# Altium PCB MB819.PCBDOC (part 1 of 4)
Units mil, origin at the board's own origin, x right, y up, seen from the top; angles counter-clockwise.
Board outline 4505 x 6805 mil, 4 copper layers (TopLayer, MidLayer1, GND, BottomLayer), stack 69.6 mil thick; 336 components, 282 nets, 1318 pads, 584 vias.
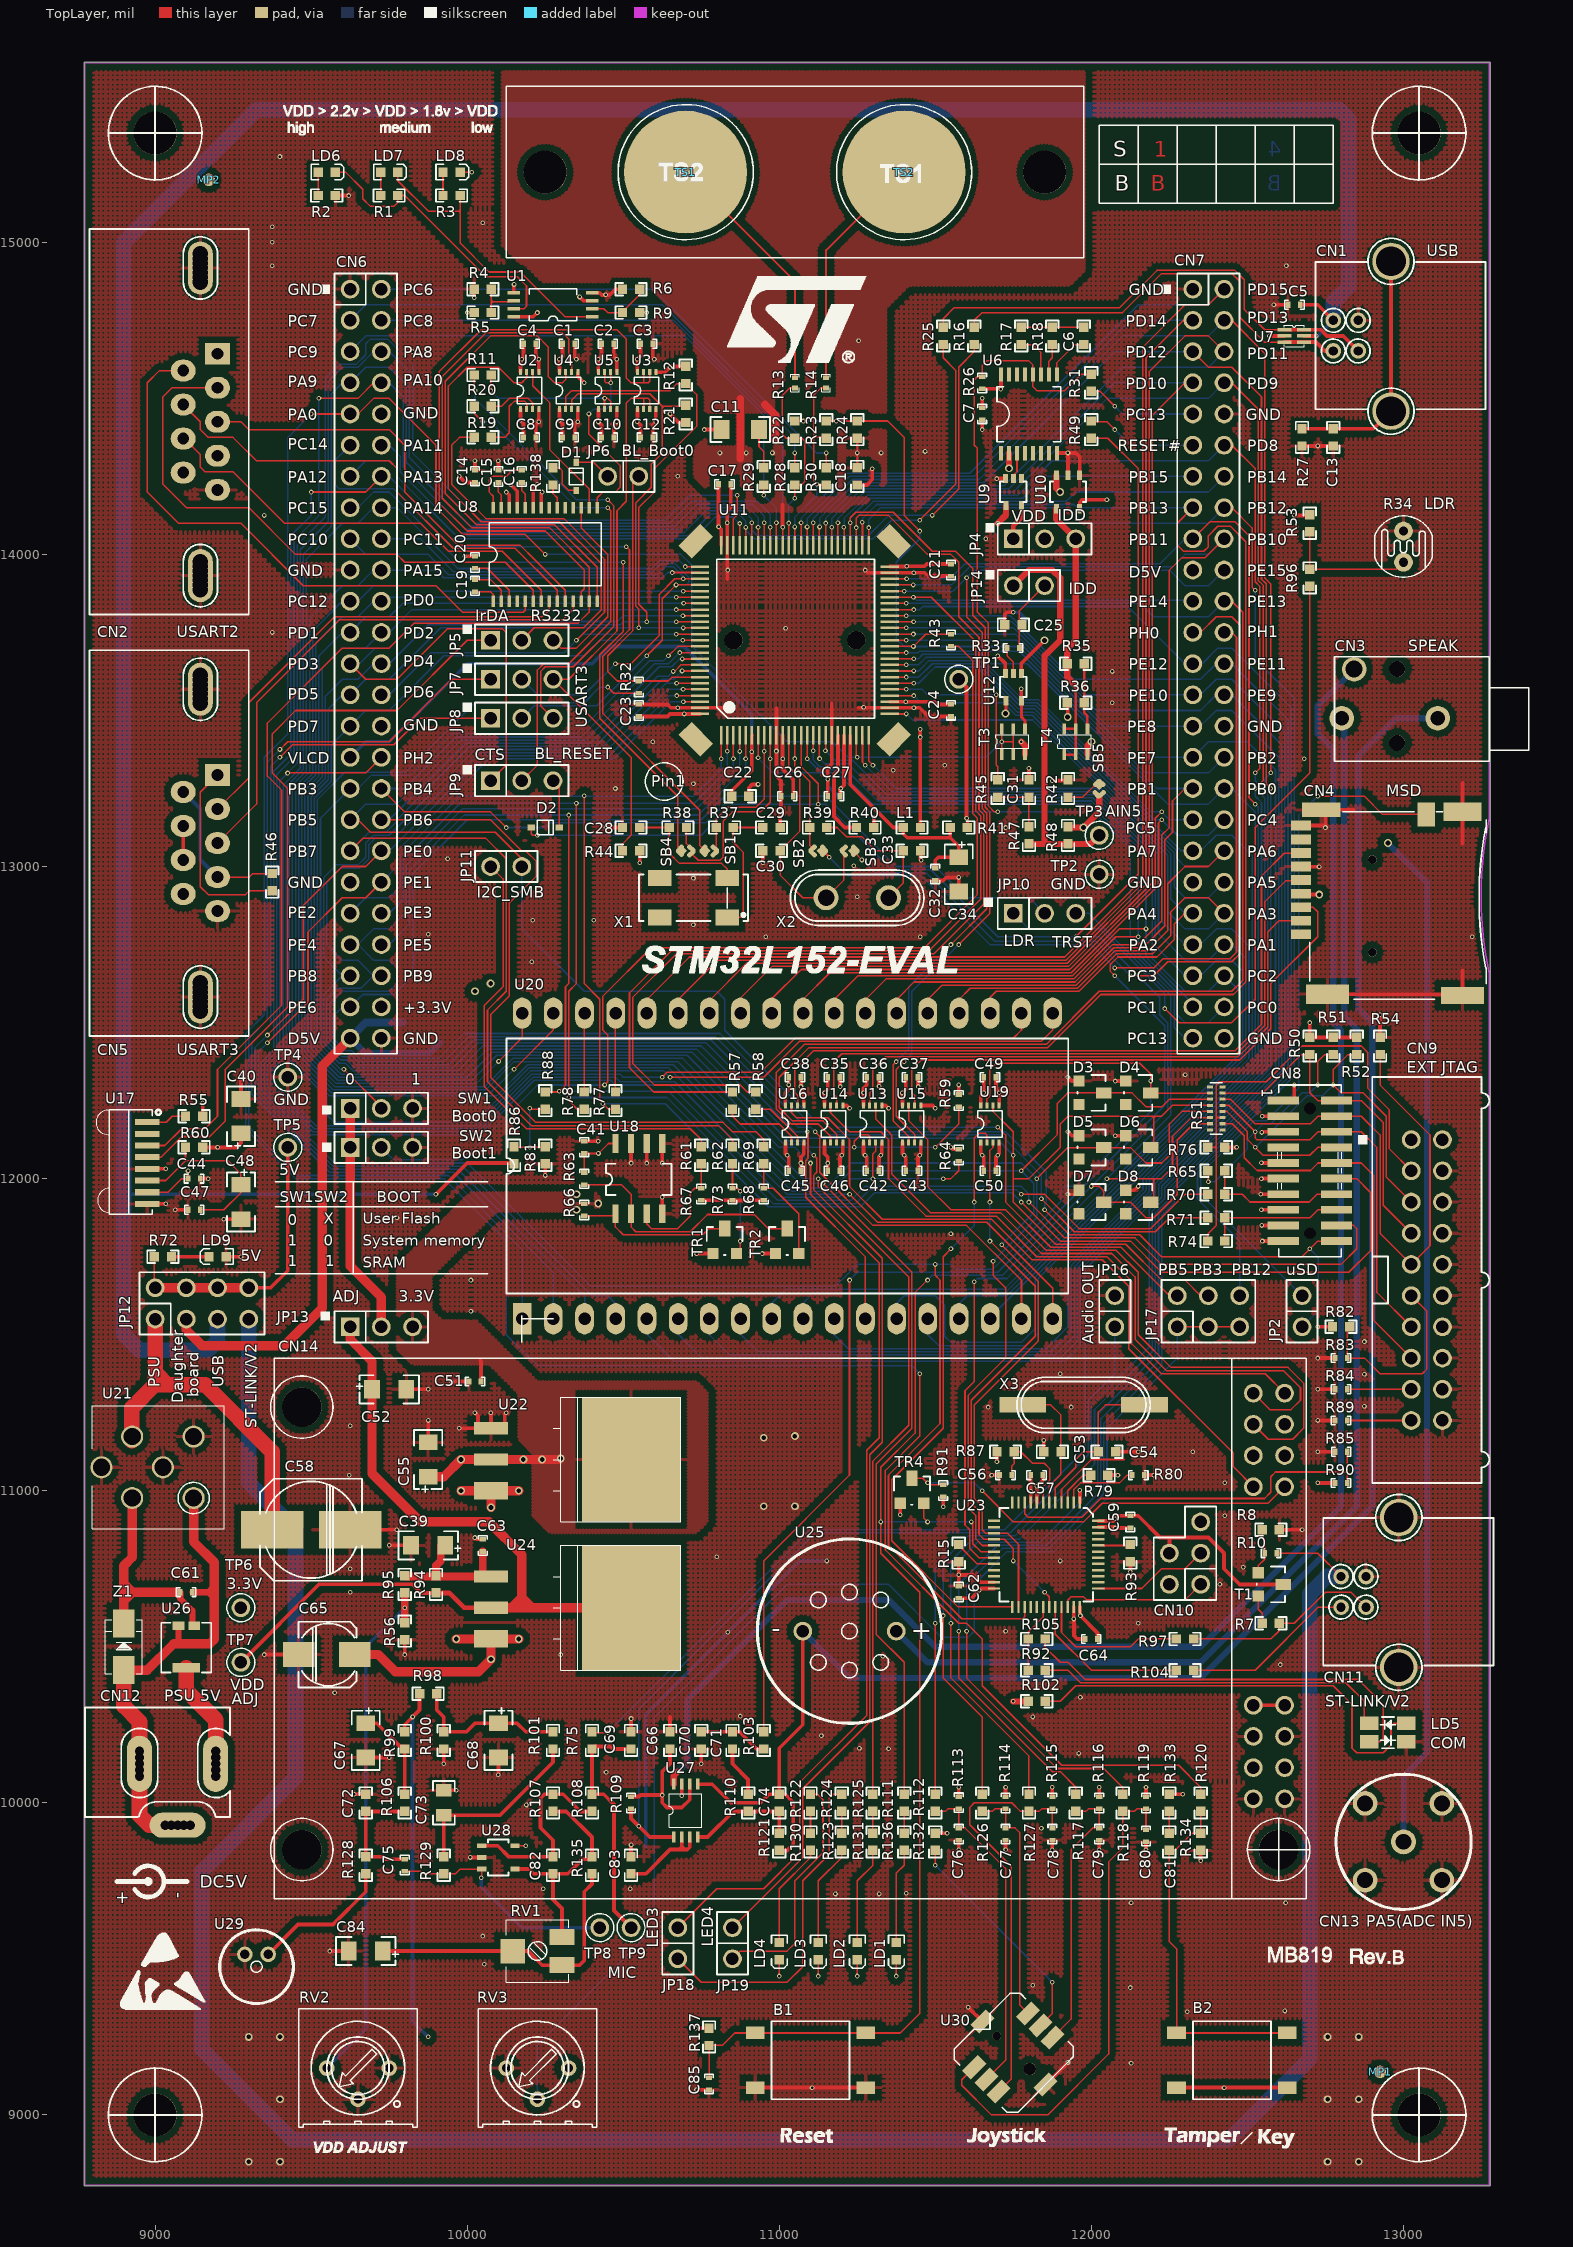
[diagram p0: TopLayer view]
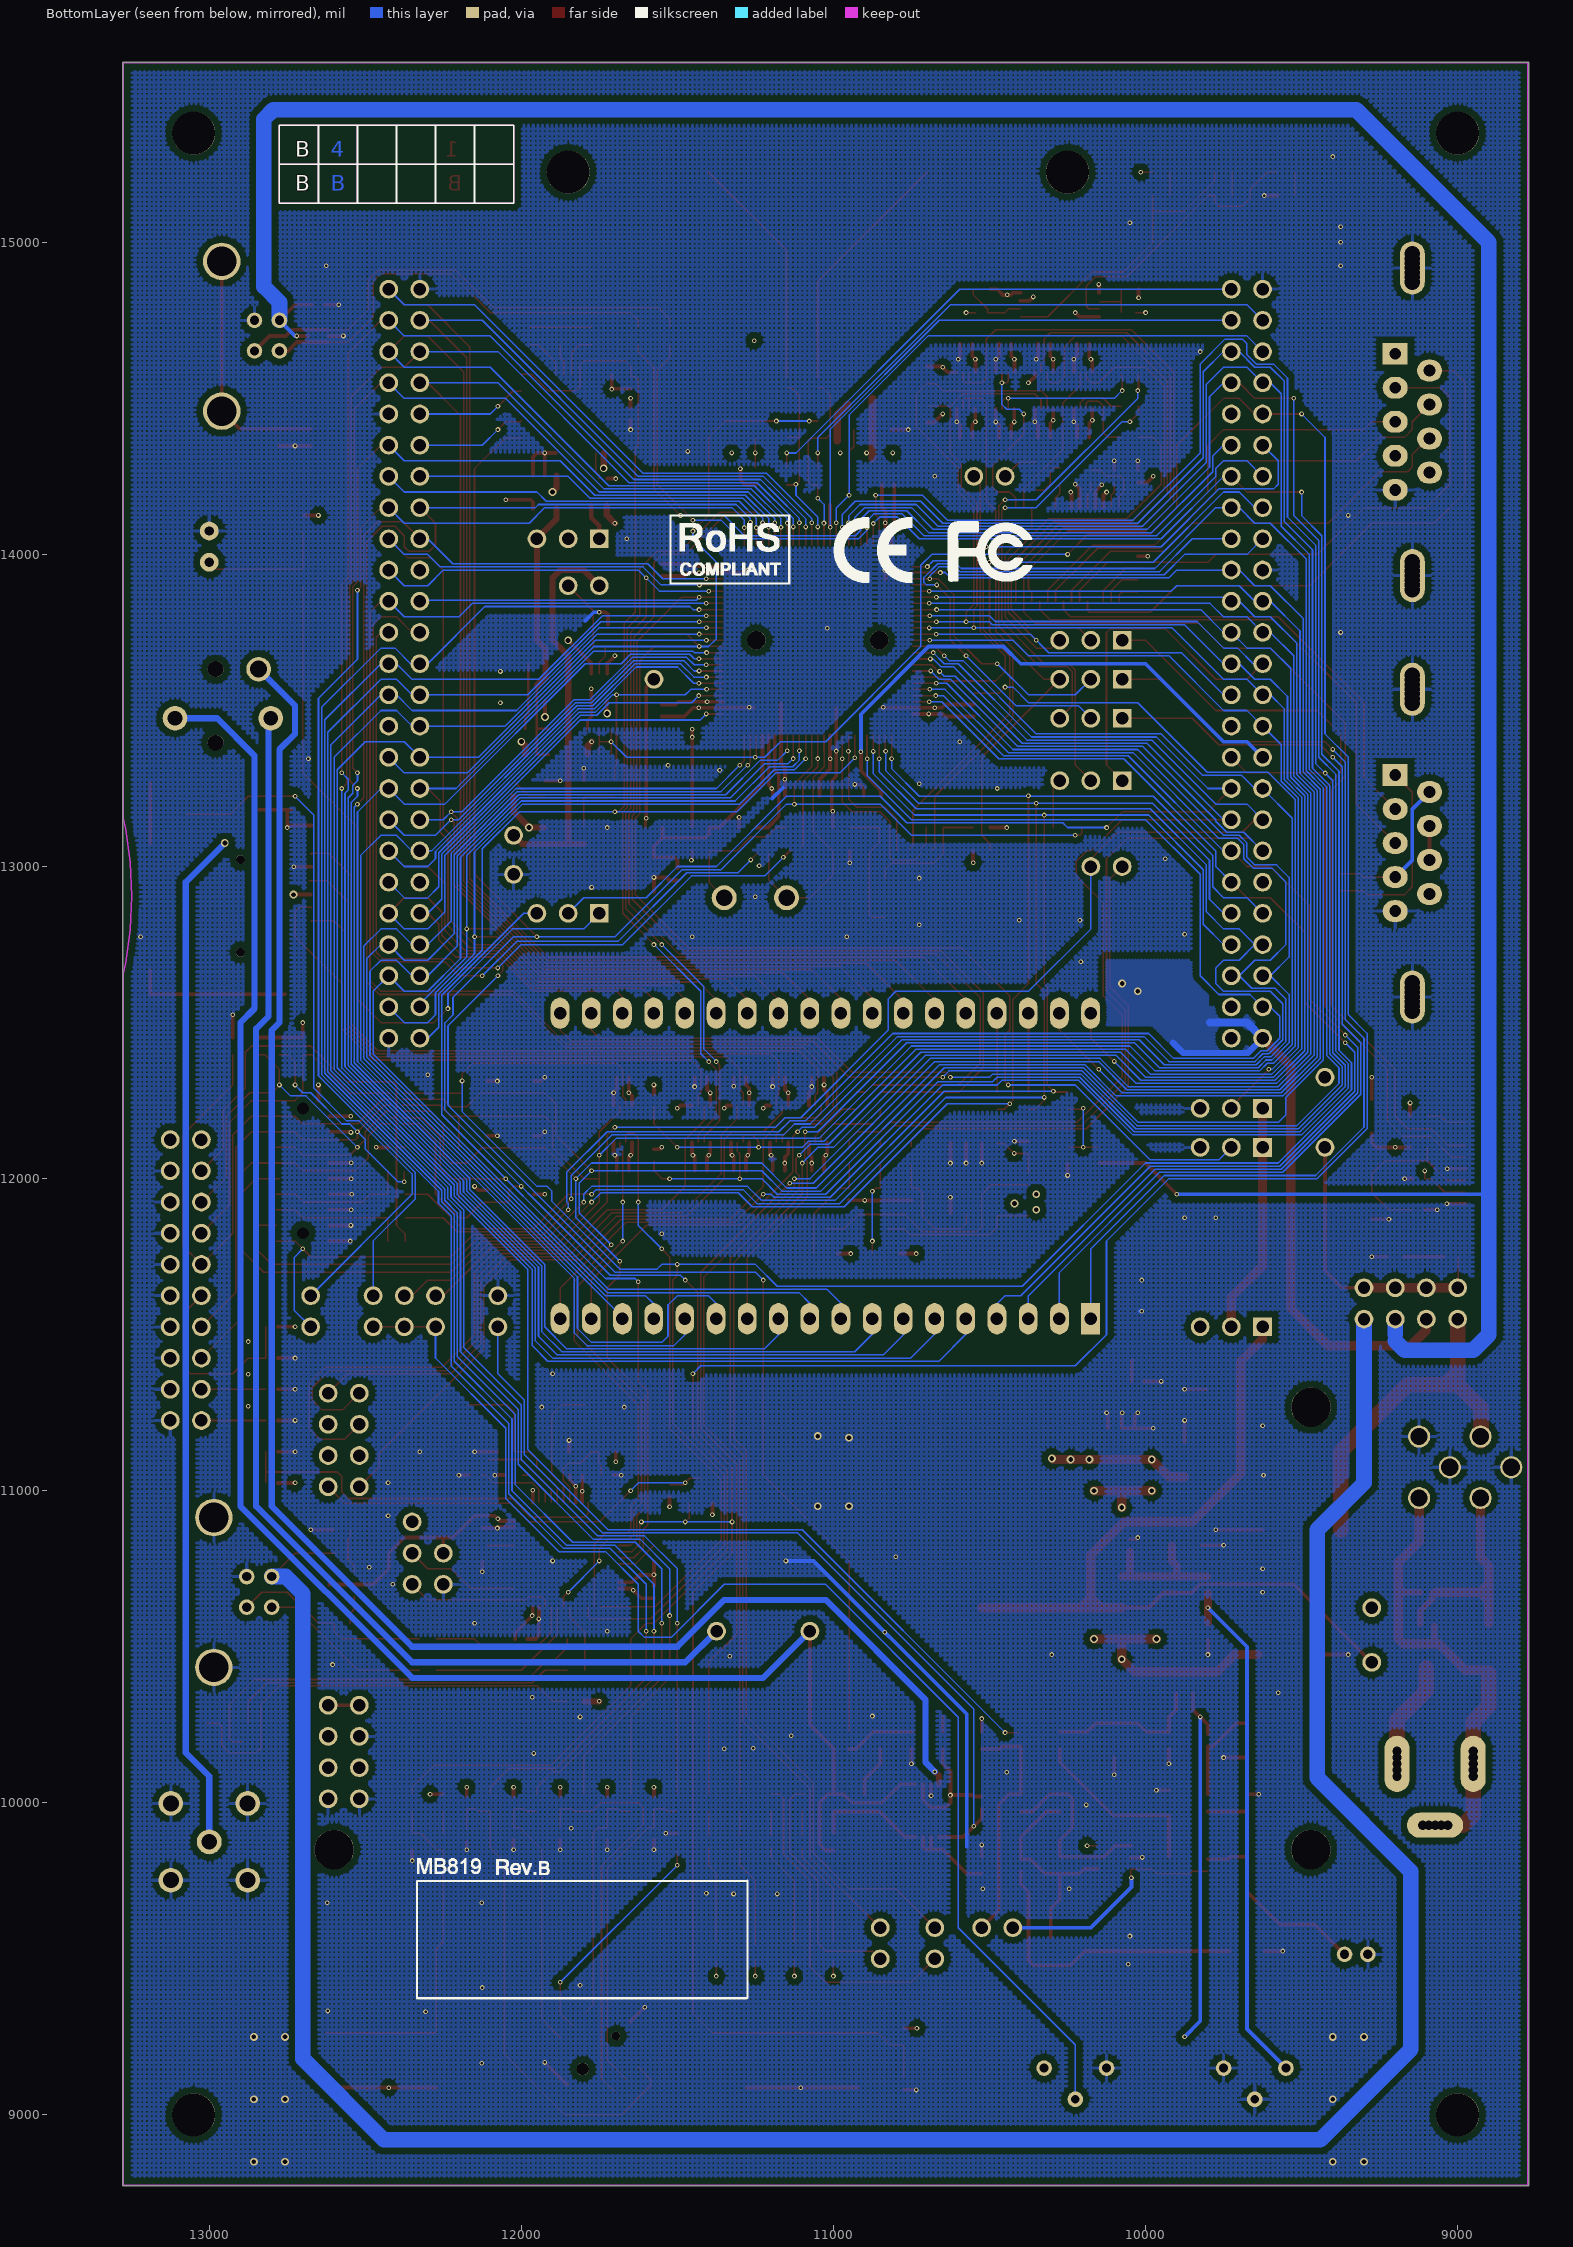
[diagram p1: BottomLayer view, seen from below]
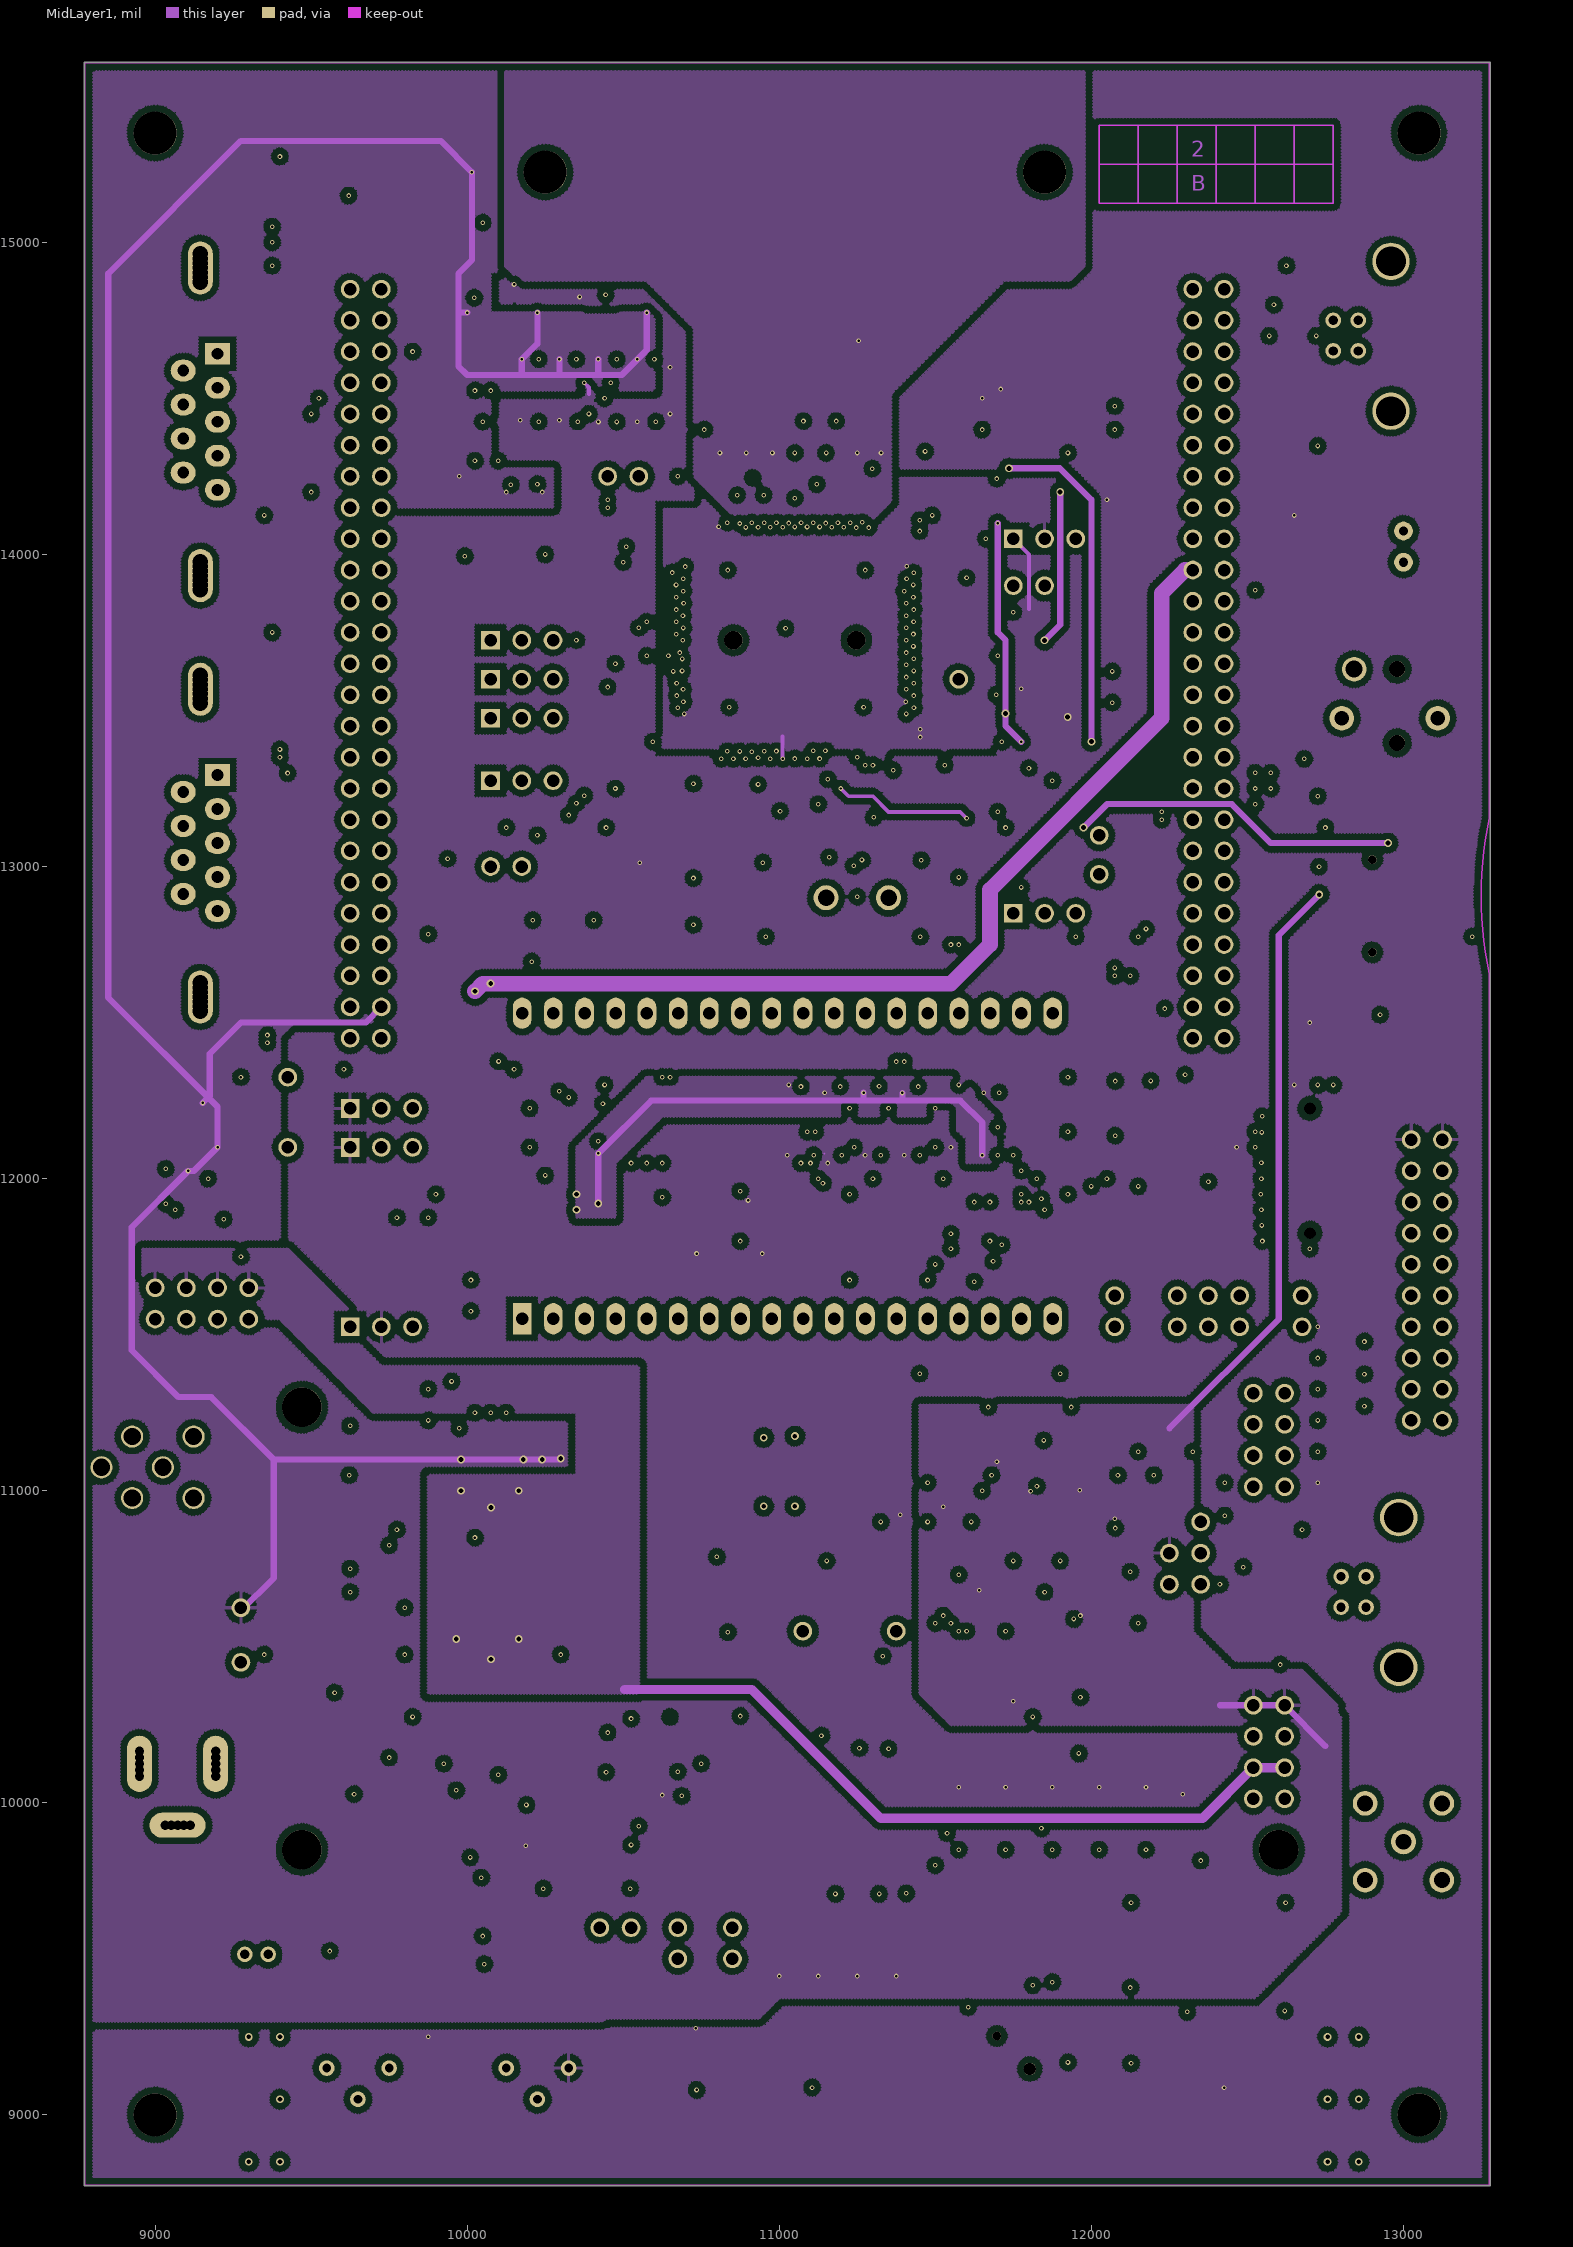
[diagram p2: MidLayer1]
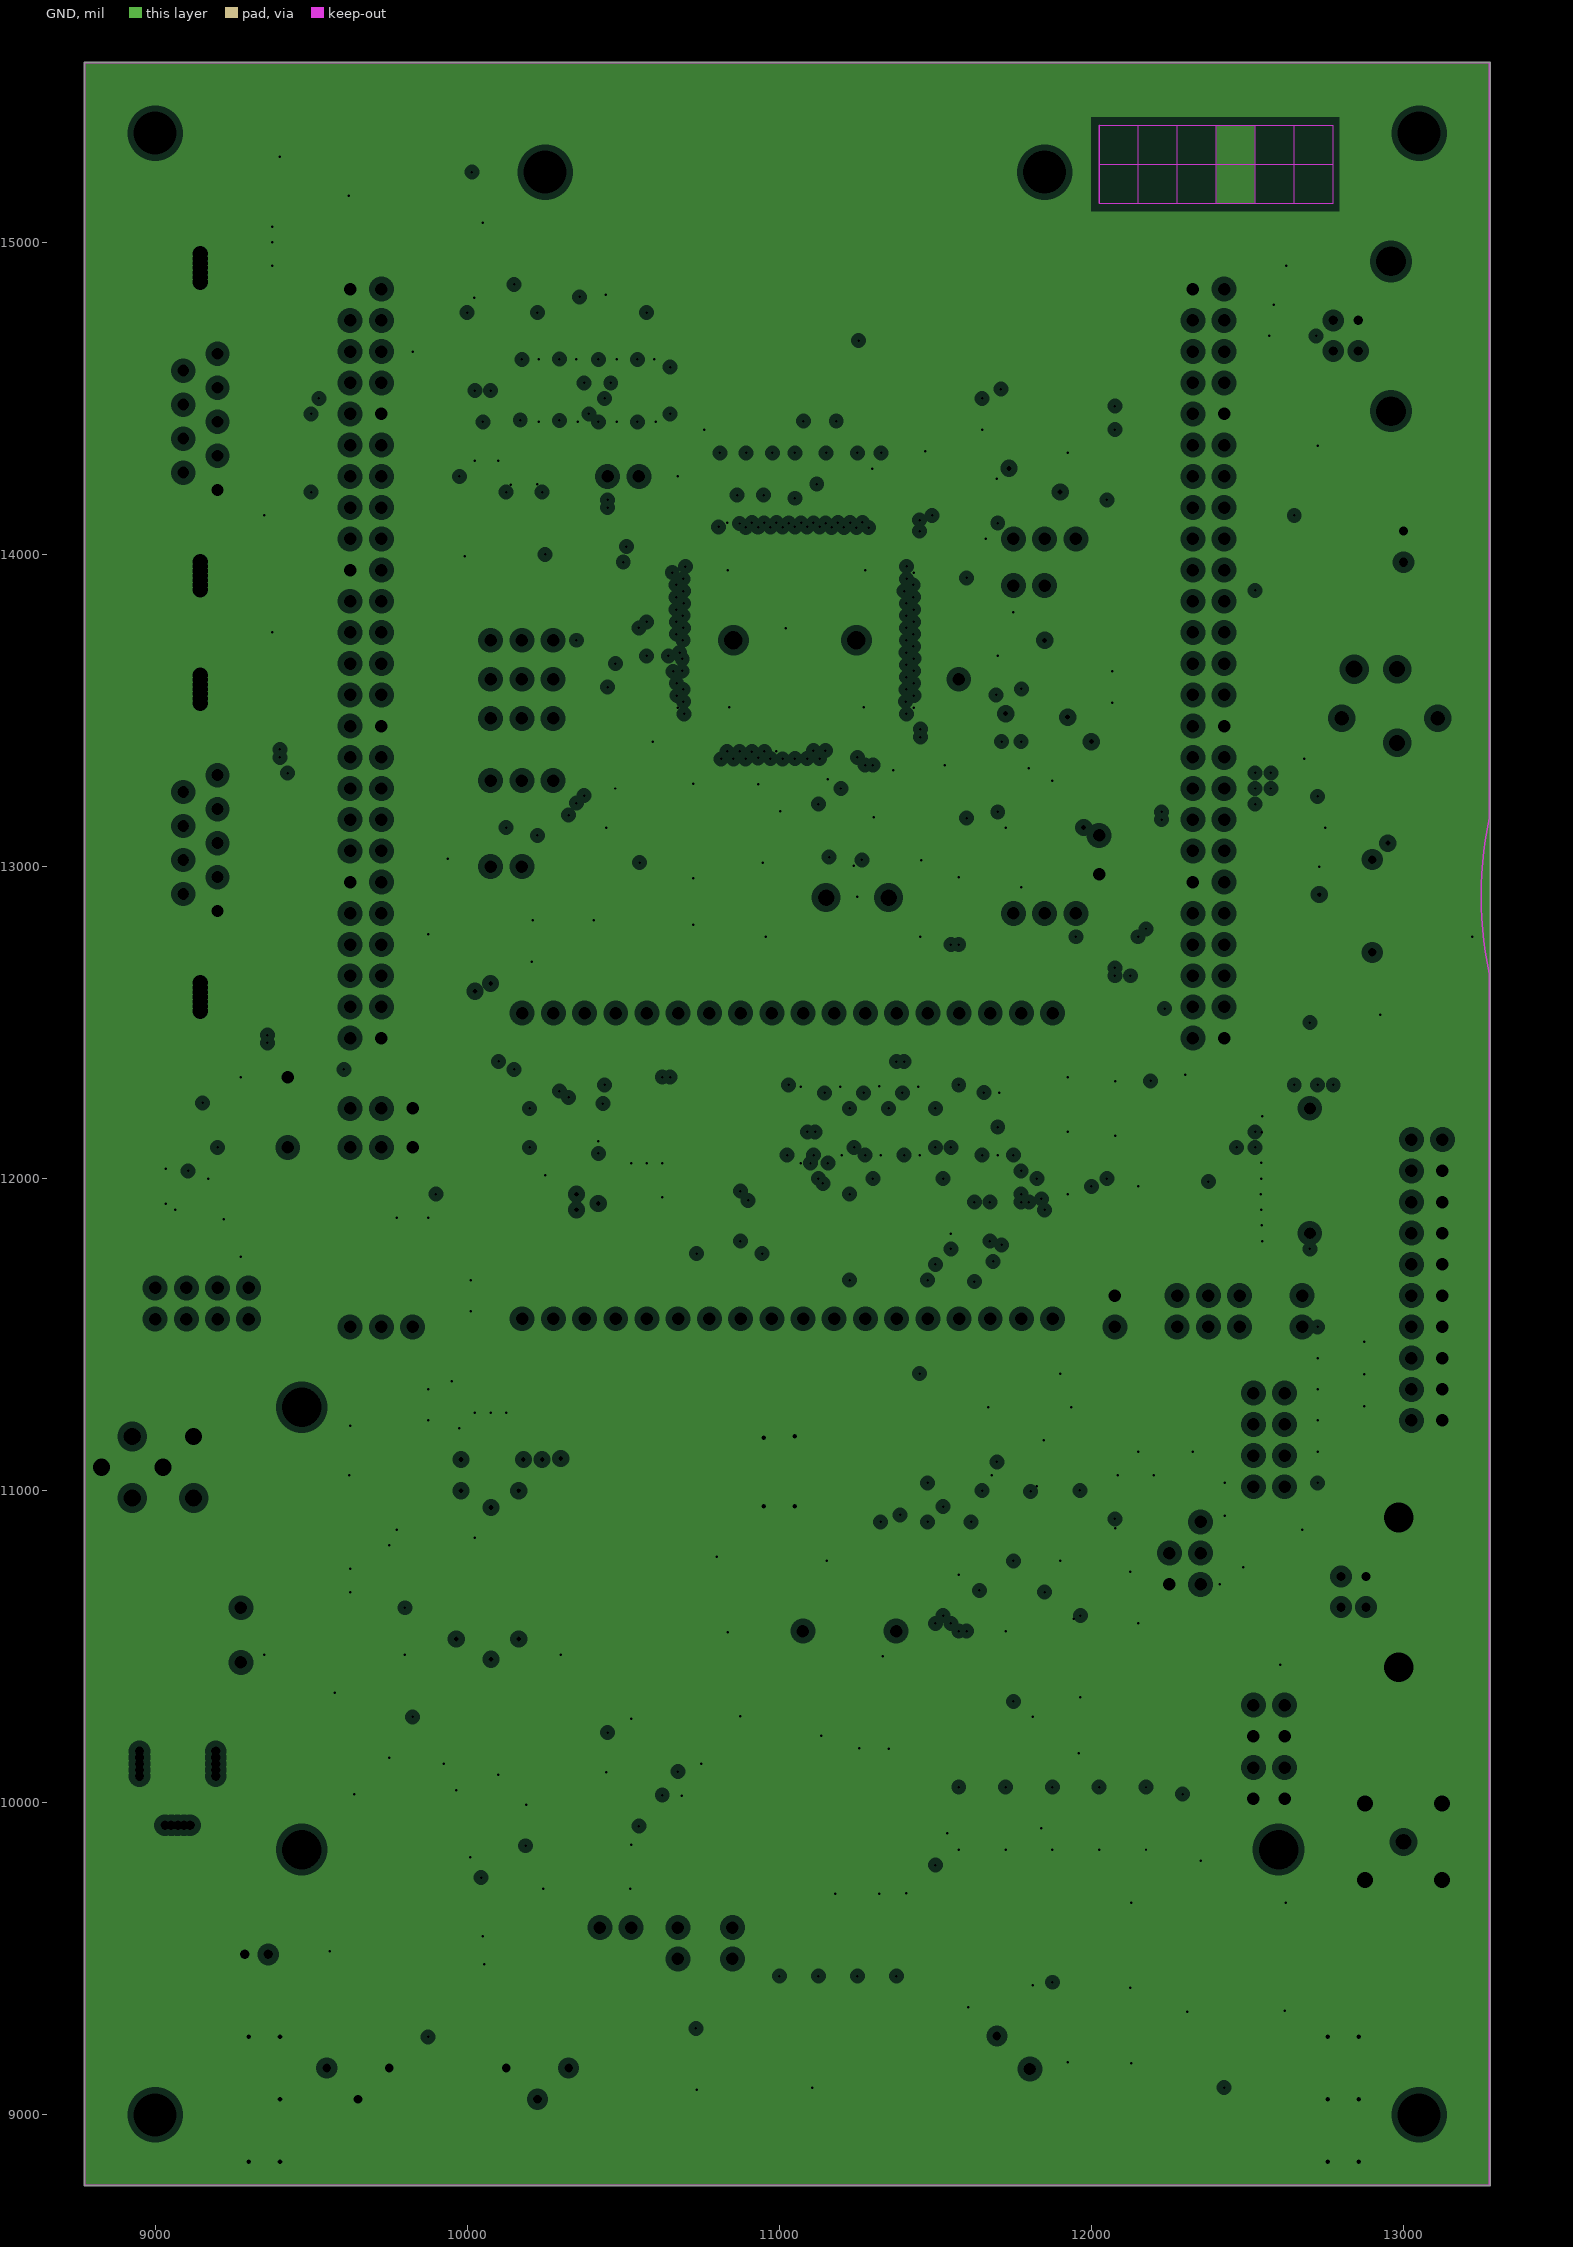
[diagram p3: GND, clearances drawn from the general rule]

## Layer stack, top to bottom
TopLayer: signal copper 1.4
Dielectric: core 4, FR-4, Dk 4.8
MidLayer1: signal copper 1.4
Dielectric: prepreg 55, FR-4, Dk 4.8
GND: plane copper 1.4, net GND
Dielectric: core 5, FR-4, Dk 4.8
BottomLayer: signal copper 1.4

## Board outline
8772.5,8772.5 13277.5,8772.5 13277.5,15577.5 8772.5,15577.5

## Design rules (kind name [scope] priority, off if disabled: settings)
Clearance Clearance_5 [HasFootprint('TS_PAD') vs (InPoly)] p1: gap=39.37
Clearance Clearance_1 [(InPoly)] p2: gap=20
Clearance [All] p3: gap=5
ComponentClearance [All] p1 off: gap=10 collisioncheckmode=0
PlaneClearance [All] p1: clearance=20
PlaneConnect [All] p1: planeconnectstyle=Relief reliefexpansion=20 reliefentries=4 reliefconductorwidth=10 reliefairgap=10
PolygonConnect [All] p1: connectstyle=Relief reliefconductorwidth=10 reliefentries=4 polygonreliefangle="90 Angle"
RoutingLayers [All] p1: top layer=Horizontal mid layer 1="Not Used" bottom layer=Vertical
RoutingVias RoutingVias_1 [All] p1: holewidth=8 width=15 viastyle="Through Hole" minholewidth=8 minwidth=15 maxholewidth=28 maxwidth=50
SolderMaskExpansion [All] p1: expansion=4
TestPointUsage [All] p1: valid=0 allowmultiple=FALSE
Testpoint [All] p1: side=15 testpointundercomponent=TRUE minsize=40 maxsize=100 preferedsize=60 minholesize=20 maxholesize=40 preferedholesize=32 testpointgrid=1 style=1023 order=1234567890
Width Width_8 [InNet('VDD_ADJ')] p1: maxlimit=300 minlimit=5 preferedwidth=12
Width Width_7 [InNet('VDD')] p2: maxlimit=300 minlimit=5 preferedwidth=12
Width Width_6 [InNet('U5V')] p3: maxlimit=300 minlimit=5 preferedwidth=12
Width Width_11 [InNet('VLCD')] p4: maxlimit=300 minlimit=5 preferedwidth=12
Width Width_10 [InNet('VDDA')] p5: maxlimit=300 minlimit=5 preferedwidth=12
Width Width_9 [InNet('VDD_MCU')] p6: maxlimit=300 minlimit=5 preferedwidth=12
Width Width_2 [InNet('+5V')] p7: maxlimit=300 minlimit=5 preferedwidth=30
Width [InNet('+3V3')] p8: maxlimit=300 minlimit=5 preferedwidth=20
Width Width_3 [InNet('D5V')] p9: maxlimit=300 minlimit=5 preferedwidth=20
Width Width_5 [InNet('GND')] p10: maxlimit=300 minlimit=5 preferedwidth=12
Width Width_4 [InNet('E5V')] p11: maxlimit=300 minlimit=5 preferedwidth=12
Width Width_1 [All] p12: maxlimit=50 minlimit=5 preferedwidth=5
14 further rules are at their usual default settings.

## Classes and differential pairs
component class MB819: MP1 MP2
net class PH[0..2]: PH0 PH1 PH2 PH[0..2]0 PH[0..2]1 PH[0..2]2
component class IDD_measurement: C6 C7 C25 JP4 R17 R18 R26 R33 R35 R36 T3 T4 U6 U9 U10 U12
component class MCU: B1 C17 C21 C22 C23 C24 C26 C27 C28 C29 C30 C32 C33 C34 C85 D1 D2 JP2 JP3 JP6 JP7 JP8 JP10 JP11 JP18 JP19 L1 R32 R37 R38 R39 R40 R41 R43 R77 R78 R137 SW1 SW2 TP1 U11 X1 X2
component class Peripherals: B2 C5 C13 C31 C39 C76 C77 C78 C79 C80 C81 CN1 CN13 JP1 JP17 LD6 LD7 LD8 LD9 R1 R2 R3 R4 R5 R6 R7 R8 R9 R10 R15 R16 R25 R27 R42 R45 R47 R48 R53 R56 R111 R112 R113 R114 R115 R116 R117 R118 R119 R120 R122 R123 R124 R125 R126 R127 R130 R131 R132 R133 R134 R136 RV3 SB5 T1 T2 TP2 TP3 U1 U7 U30
component class Audio: C66 C67 C68 C69 C70 C71 C72 C73 C74 C75 C82 C83 C84 CN3 JP15 JP16 R98 R99 R100 R101 R102 R103 R106 R107 R108 R109 R110 R121 R128 R129 R135 RV1 TP8 TP9 U25 U27 U28 U29
component class Power: C51 C52 C55 C58 C60 C61 C63 C65 CN12 JP12 JP13 LD9 R72 R94 R95 RV2 TP4 TP5 TP6 TP7 U21 U22 U24 U26 Z1
component class RS232_IrDA: C1 C2 C3 C4 C8 C9 C10 C12 C14 C15 C16 C19 C20 C40 C44 C47 C48 CN2 CN5 JP5 JP9 R11 R19 R20 R46 R55 R60 U2 U3 U4 U5 U8 U17
component class ST_LINK: C49 C50 C53 C54 C56 C57 C59 C62 C64 CN10 CN11 JP14 LD5 R75 R76 R79 R80 R81 R85 R86 R87 R88 R90 R91 R92 R96 R97 R104 R105 T5 T6 TR3 TR4 U19 U23 X3
component class ICC_measurement: C6 C7 C25 JP4 R17 R18 R26 R33 R34 R35 R36 T3 T4 U6 U9 U10 U12
component class TemSensor: C41 R61 R62 R63 R66 R67 R68 R69 R73 TR1 TR2 U18
component class LCD_MicroSD: C35 C36 C37 C38 C42 C43 C45 C46 CN4 CN14 R57 R58 R59 R64 U13 U14 U15 U16
component class TouchSensing: C11 C18 R13 R14 R22 R23 R24 R29 TS1 TS2
component class Extensionconnector: CN6 CN7 R28 R30 R31 R49 SB1 SB2 SB3 SB4
component class JTAG&Trace: CN8 CN9 D3 D4 D5 D6 D7 D8 R50 R51 R52 R54 R65 R70 R71 R74 R76 R77 R78 R79 R80 R82 R83 R84 R89 RS1
component class LCD_Glass: U20
net class PA[0..15]: PA0 PA1 PA2 PA3 PA4 PA5 PA6 PA7 PA8 PA9 PA10 PA11 PA12 PA13 PA14 PA15 PA[0..15]0 PA[0..15]1 PA[0..15]2 PA[0..15]3 PA[0..15]4 PA[0..15]5 PA[0..15]6 PA[0..15]7 PA[0..15]8 PA[0..15]9 PA[0..15]10 PA[0..15]11 PA[0..15]12 PA[0..15]13 PA[0..15]14 PA[0..15]15
net class PB[0..15]: PB0 PB1 PB2 PB3 PB4 PB5 PB6 PB7 PB8 PB9 PB10 PB11 PB12 PB13 PB14 PB15 PB[0..15]0 PB[0..15]1 PB[0..15]2 PB[0..15]3 PB[0..15]4 PB[0..15]5 PB[0..15]6 PB[0..15]7 PB[0..15]8 PB[0..15]9 PB[0..15]10 PB[0..15]11 PB[0..15]12 PB[0..15]13 PB[0..15]14 PB[0..15]15
net class PC[0..15]: PA0 PC0 PC1 PC2 PC3 PC4 PC5 PC6 PC7 PC8 PC9 PC10 PC11 PC12 PC14 PC15 PC[0..15]0 PC[0..15]1 PC[0..15]2 PC[0..15]3 PC[0..15]4 PC[0..15]5 PC[0..15]6 PC[0..15]7 PC[0..15]8 PC[0..15]9 PC[0..15]10 PC[0..15]11 PC[0..15]12 PC[0..15]13 PC[0..15]14 PC[0..15]15
net class PD[0..15]: PD0 PD1 PD2 PD3 PD4 PD5 PD6 PD7 PD8 PD9 PD10 PD11 PD12 PD13 PD14 PD15 PD[0..15]0 PD[0..15]1 PD[0..15]2 PD[0..15]3 PD[0..15]4 PD[0..15]5 PD[0..15]6 PD[0..15]7 PD[0..15]8 PD[0..15]9 PD[0..15]10 PD[0..15]11 PD[0..15]12 PD[0..15]13 PD[0..15]14 PD[0..15]15
net class PE[0..15]: PE0 PE1 PE2 PE3 PE4 PE5 PE6 PE7 PE8 PE9 PE10 PE11 PE12 PE13 PE14 PE15 PE[0..15]0 PE[0..15]1 PE[0..15]2 PE[0..15]3 PE[0..15]4 PE[0..15]5 PE[0..15]6 PE[0..15]7 PE[0..15]8 PE[0..15]9 PE[0..15]10 PE[0..15]11 PE[0..15]12 PE[0..15]13 PE[0..15]14 PE[0..15]15
net class PF[0..2]: PF[0..2]0 PF[0..2]1 PF[0..2]2 PH0 PH1 PH2
net class SEG[0..43]: SEG0 SEG1 SEG2 SEG3 SEG4 SEG5 SEG6 SEG7 SEG8 SEG9 SEG10 SEG11 SEG12 SEG13 SEG14 SEG15 SEG16 SEG17 SEG18 SEG19 SEG20 SEG21 SEG22 SEG23 SEG24 SEG25 SEG26 SEG27 SEG28 SEG29 SEG30 SEG31 SEG32 SEG33 SEG34 SEG35 SEG36 SEG37 SEG38 SEG39 SEG40 SEG41 SEG42 SEG43 SEG[0..43]0 SEG[0..43]1 SEG[0..43]2 SEG[0..43]3 SEG[0..43]4 SEG[0..43]5 SEG[0..43]6 SEG[0..43]7 SEG[0..43]8 SEG[0..43]9 SEG[0..43]10 SEG[0..43]11 SEG[0..43]12 SEG[0..43]13 SEG[0..43]14 SEG[0..43]15 SEG[0..43]16 SEG[0..43]17 SEG[0..43]18 SEG[0..43]19 SEG[0..43]20 SEG[0..43]21 SEG[0..43]22 SEG[0..43]23 SEG[0..43]24 SEG[0..43]25 SEG[0..43]26 SEG[0..43]27 SEG[0..43]28 SEG[0..43]29 SEG[0..43]30 SEG[0..43]31 SEG[0..43]32 SEG[0..43]33 SEG[0..43]34 SEG[0..43]35 SEG[0..43]36 SEG[0..43]37 SEG[0..43]38 SEG[0..43]39 SEG[0..43]40 SEG[0..43]41 SEG[0..43]42 SEG[0..43]43
net class COM[0..3]: COM0 COM1 COM2 COM3 COM[0..3]0 COM[0..3]1 COM[0..3]2 COM[0..3]3

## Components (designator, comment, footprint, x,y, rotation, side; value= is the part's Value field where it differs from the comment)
B1 "RESET" PB10 11100,9175 r0 top
B2 "WKUP" PB10 12450,9175 r0 top
C1 "100nF" 0402C 10325,14675 r0 top
C2 "100nF" 0402C 10450,14675 r0 top
C3 "100nF" 0402C 10575,14675 r0 top
C4 "100nF" 0402C 10200,14675 r0 top
C5 "100nF" 0402C 12650,14800 r0 top
C6 "1nF" 0603C 11975,14700 r270 top
C7 "100nF" 0402C 11650,14450 r90 top
C8 "100nF" 0402C 10200,14375 r180 top
C9 "100nF" 0402C 10325,14375 r0 top
C10 "100nF" 0402C 10450,14375 r0 top
C11 "33nF(1206)" 1206C 10875,14400 r180 top
C12 "100nF" 0402C 10575,14375 r0 top
C13 "4.7nF" 0603C 12775,14375 r270 top
C14 "100nF" 0402C 10025,14250 r90 top
C15 "100nF" 0402C 10100,14250 r270 top
C16 "100nF" 0402C 10175,14250 r270 top
C17 "100nF" 0402C 10825,14225 r180 top
C18 "[N/A]" 0603C 11250,14250 r90 top
C19 "100nF" 0402C 10025,13900 r270 top
C20 "100nF" 0402C 10025,13975 r270 top
C21 "100nF" 0402C 11550,13950 r90 top
C22 "1uF" 0603C 10875,13225 r180 top
C23 "100nF" 0402C 10550,13500 r270 top
C24 "100nF" 0402C 11550,13500 r90 top
C25 "1uF" 0603C 11750,13775 r0 top
C26 "100nF" 0402C 11025,13225 r0 top
C27 "100nF" 0402C 11175,13225 r0 top
C28 "6.8pF" 0603C 10525,13125 r0 top
C29 "6.8pF" 0603C 10975,13125 r180 top
C30 "20pF" 0603C 10975,13050 r0 top
C31 "[N/A]" 0603C 11800,13250 r90 top
C32 "100nF" 0402C 11500,12975 r90 top
C33 "20pF" 0603C 11425,13050 r180 top
C34 "1uF" TAN-A 11575,12975 r90 top
C35 "100nF" 0402C 11175,12325 r0 top
C36 "100nF" 0402C 11300,12325 r0 top
C37 "100nF" 0402C 11425,12325 r0 top
C38 "100nF" 0402C 11050,12325 r0 top
C39 "1uF" TAN-A 9875,10825 r0 top
C40 "4.7uF" TAN-A 9275,12200 r270 top
C41 "100nF" 0402C 10375,12100 r90 top
C42 "100nF" 0402C 11300,12025 r0 top
C43 "100nF" 0402C 11425,12025 r0 top
C44 "100nF" 0402C 9125,12000 r180 top
C45 "100nF" 0402C 11050,12025 r180 top
C46 "100nF" 0402C 11175,12025 r0 top
C47 "100nF" 0402C 9125,11900 r0 top
C48 "4.7uF" TAN-A 9275,11925 r90 top
C49 "100nF" 0402C 11675,12325 r180 top
C50 "100nF" 0402C 11675,12025 r0 top
C51 "100nF" 0402C 10025,11350 r0 top
C52 "10uF" TAN-A 9750,11325 r180 top
C53 "Cap" 0603R 11875,11125 r180 top
C54 "Cap" 0603R 12050,11125 r0 top
C55 "10uF" TAN-A 9875,11100 r270 top
C56 "100nF" 0402C 11725,11050 r180 top
C57 "100nF" 0402C 11825,11050 r180 top
C58 "220uF" C310M 9500,10875 r180 top
C59 "100nF" 0402C 12125,10900 r270 top
C61 "100nF" 0402C 9100,10675 r180 top
C62 "100nF" 0402C 11575,10675 r90 top
C63 "100nF" 0402C 10050,10825 r270 top
C64 "100nF" 0402C 12000,10525 r180 top
C65 "47uF" C200M 9550,10475 r0 top
C66 "1uF" 0603C 10650,10200 r270 top
C67 "10uF" TAN-A 9675,10200 r90 top
C68 "4.7uF" TAN-A 10100,10200 r90 top
C69 "[N/A]" 0603C 10525,10200 r270 top
C70 "[N/A]" 0603C 10750,10200 r270 top
C71 "470nF" 0603C 10850,10200 r90 top
C72 "47pF" 0603C 9675,10000 r270 top
C73 "2.2uF" 0805C 9925,10000 r270 top
C74 "330pF" 0603C 11000,10000 r270 top
C75 "100nF" 0402C 9800,9800 r90 top
C76 "100nF" 0402C 11575,9900 r270 top
C77 "100nF" 0402C 11725,9900 r270 top
C78 "100nF" 0402C 11875,9900 r270 top
C79 "100nF" 0402C 12025,9900 r270 top
C80 "100nF" 0402C 12175,9894.5 r270 top
C81 "[N/A]" 0603C 12250,9875 r90 top
C82 "180pF" 0603C 10275,9800 r270 top
C83 "1uF" 0603C 10525,9800 r270 top
C84 "4.7uF" TAN-A 9675,9525 r0 top
C85 "100nF" 0402C 10775,9100 r270 top
CN1 "USB-typeB connector" USB-B 12775,14750 r90 top
CN2 "DB9-male USART2" DB9/M 9200,14425 r90 top
CN3 "ST-613" PJST-613 13275,13475 r180 top
CN4 "PJS008-2000 (SMS064FF or SMS128FF)" MSD(PJS008) 12900,12725 r0 top
CN5 "DB9-male USART3" DB9/M 9200,13075 r90 top
CN6 "Header 25X2" 2*25P 9625,14850 r0 top locked
CN7 "Header 25X2" 2*25P 12325,14850 r0 top locked
CN8 "FTSH-110-01-L-DV" FTSH-110-01-L-DV 12700,12025 r270 top
CN9 "JTAG" IDC20S 13025,12125 r0 top
CN10 "JTAG" 2*3P#1 12350,10700 r180 top
CN11 "USB-typeB connector" USB-B 12800,10725 r90 top
CN12 "DC-10B" DC10B 8950,10125 r0 top
CN13 "VB334" VB334 13000,9875 r0 top
CN14 "2.4\" LCD connector (MB542 with AM240320L8TNQW-00H)" MB542 12600,9850 r0 top
D1 "BAT60JFILM" SOD-323 10350,14250 r270 top
D2 "BAT60JFILM" SOD-323 10250,13125 r180 top
D3 "Z5V1" SOT-23 12000,12275 r180 top
D4 "Z5V1" SOT-23 12150,12275 r180 top
D5 "Z5V1" SOT-23 12000,12100 r180 top
D6 "Z5V1" SOT-23 12150,12100 r180 top
D7 "Z5V1" SOT-23 12000,11925 r180 top
D8 "Z5V1" SOT-23 12150,11925 r180 top
JP2 "" SIP2 12675,11625 r270 top
JP4 "" SIP3 11750,14050 r0 top
JP5 "" SIP3 10075,13725 r0 top
JP6 "" SIP2 10550,14250 r180 top
JP7 "" SIP3 10075,13600 r0 top
JP8 "" SIP3 10075,13475 r0 top
JP9 "" SIP3 10075,13275 r0 top
JP10 "" SIP3 11750,12850 r0 top
JP11 "" SIP2 10175,13000 r180 top
JP12 "Header 4X2" 2*4P 9000,11550 r90 top
JP13 "" SIP3 9625,11525 r0 top
JP14 "" SIP2 11750,13900 r0 top
JP16 "" SIP2 12075,11525 r90 top
JP17 "Header 3X2" 2*3P#2 12275,11525 r90 top
JP18 "" SIP2 10675,9500 r90 top
JP19 "" SIP2 10850,9500 r90 top
L1 "BEAD" 0603L 11425,13125 r0 top
LD1 "Green" 0603D 11375,9525 r270 top
LD2 "Orange" 0603D 11250,9525 r270 top
LD3 "Red" 0603D 11125,9525 r270 top
LD4 "Blue" 0603D 11000,9525 r270 top
LD5 "HSMF-A201-A00J1" LED2-28*32 12950,10225 r90 top
LD6 "Green" 0603D 9550,15225 r0 top
LD7 "Orange" 0603D 9750,15225 r0 top
LD8 "RED" 0603D 9950,15225 r0 top
LD9 "red" 0603D 9200,11750 r180 top
MP1 "" markpoint_1.0 12925,9138 r0 top
MP2 "" markpoint_1.0 9172,15200 r0 top
R1 "510" 0603R 9750,15150 r180 top
R2 "510" 0603R 9550,15150 r180 top
R3 "510" 0603R 9950,15150 r180 top
R4 "2K" 0603R 10050,14850 r180 top
R5 "1K" 0603R 10050,14775 r0 top
R6 "1K2" 0603R 10525,14850 r180 top
R7 "1.5K" 0603R 12575,10575 r180 top
R8 "36K" 0603R 12575,10875 r180 top
R9 "1K" 0603R 10525,14775 r180 top
R10 "10K" 0402R#1 12575,10800 r0 top
R11 "0" 0603R 10050,14575 r180 top
R12 "100K" 0603R 10700,14575 r270 top
R13 "10K" 0402R#2 11050,14550 r270 top
R14 "10K" 0402R#2 11150,14550 r270 top
R15 "100K" 0603R 11575,10800 r90 top
R16 "0" 0603R 11625,14700 r270 top
R17 "30K" 0603R 11775,14700 r270 top
R18 "15K" 0603R 11875,14700 r270 top
R19 "0" 0603R 10050,14375 r180 top
R20 "0" 0603R 10050,14475 r180 top
R21 "100K" 0603R 10700,14450 r90 top
R22 "[N/A]" 0603R 11050,14400 r270 top
R23 "[N/A]" 0603R 11150,14400 r270 top
R24 "[N/A]" 0603R 11250,14400 r270 top
R25 "0" 0603R 11525,14700 r270 top
R26 "10K" 0402R#1 11650,14550 r270 top
R27 "1M" 0603R 12675,14375 r270 top
R28 "[N/A]" 0603R 11050,14250 r90 top
R29 "0" 0603R 10950,14250 r270 top
R30 "[N/A]" 0603R 11150,14250 r270 top
R31 "820" 0603R 12000,14550 r90 top
R32 "10K" 0402R#1 10550,13575 r90 top
R33 "10K" 0402R#1 11750,13700 r180 top
R34 "VT9ON1" PVT901 13000,14025 r0 top
R35 "1K[1%]" 0603R 11950,13650 r180 top
R36 "1[1%]" 0603R 11950,13525 r0 top
R37 "0" 0603R 10825,13125 r0 top
R38 "0" 0603R 10675,13125 r180 top
R39 "0" 0603R 11125,13125 r180 top
R40 "0" 0603R 11275,13125 r0 top
R41 "50" 0603R 11575,13125 r0 top
R42 "50" 0603R 11925,13250 r270 top
R43 "10K" 0402R#1 11550,13725 r90 top
R44 "100K" 0603R 10525,13050 r180 top
R45 "0" 0603R 11700,13250 r90 top
R46 "[N/A]" 0603R 9375,12950 r90 top
R47 "0" 0603R 11800,13100 r90 top
R48 "0" 0603R 11925,13100 r270 top
R49 "820" 0603R 12000,14400 r90 top
R50 "[N/A]" 0603R 12700,12425 r270 top
R51 "[N/A]" 0603R 12775,12425 r270 top
R52 "[N/A]" 0603R 12850,12425 r270 top
R53 "100K" 0603R 12700,14100 r270 top
R54 "[N/A]" 0603R 12925,12425 r90 top
R55 "5" 0603R 9125,12200 r0 top
R56 "2K2[1%]" 0603R 9800,10550 r90 top
R57 "0" 0603R 10850,12250 r90 top
R58 "0" 0603R 10925,12250 r90 top
R59 "10K" 0402R#1 11575,12250 r90 top
R60 "47" 0603R 9125,12100 r0 top
R61 "0" 0603R 10750,12075 r270 top
R62 "0" 0603R 10850,12075 r90 top
R63 "4K7" 0402R#1 10375,12000 r270 top
R64 "10K" 0402R#1 11575,12075 r90 top
R65 "[N/A]" 0603R 12400,12025 r0 top
R66 "4K7" 0402R#1 10375,11900 r270 top
R67 "4K7" 0402R#1 10750,11950 r90 top
R68 "4K7" 0402R#1 10950,11950 r90 top
R69 "0" 0603R 10950,12075 r90 top
R70 "0" 0603R 12400,11950 r0 top
R71 "0" 0603R 12400,11875 r0 top
R72 "1K" 0603R 9025,11750 r0 top
R73 "4K7" 0402R#1 10850,11950 r90 top
R74 "[N/A]" 0603R 12400,11800 r0 top
R75 "0" 0603R 10400,10200 r90 top
R76 "[N/A]" 0603R 12400,12100 r180 top
R77 "0" 0603R 10475,12250 r270 top
R78 "0" 0603R 10375,12250 r270 top
R79 "[N/A]" 0603R 12025,11050 r0 top
R80 "10K" 0402R#1 12150,11050 r0 top
R81 "220K" 0603R 10250,12075 r90 top
R82 "[N/A]" 0603R 12800,11525 r0 top
R83 "10K" 0402R#1 12800,11425 r180 top
R84 "10K" 0402R#1 12800,11325 r180 top
R85 "4K7" 0402R#1 12800,11125 r0 top
R86 "100K" 0603R 10150,12075 r270 top
R87 "100K" 0603R 11725,11125 r0 top
R88 "0" 0603R 10250,12250 r90 top
R89 "10K" 0402R#1 12800,11225 r180 top
R90 "4K7" 0402R#1 12800,11025 r180 top
R91 "4K7" 0402R#1 11525,11000 r90 top
R92 "50" 0603R 11825,10425 r180 top
R93 "100K" 0603R 12125,10800 r270 top
R94 "124[1%]" 0603R 9900,10700 r90 top
R95 "40.2[1%]" 0603R 9800,10700 r90 top
R96 "0" 0603R 12700,13925 r90 top
R97 "22" 0603R 12300,10525 r180 top
R98 "100K" 0603R 9875,10350 r180 top
R99 "1K" 0603R 9800,10200 r270 top
R100 "100K" 0603R 9925,10200 r90 top
R101 "15K" 0603R 10275,10200 r90 top
R102 "0" 0603R 11825,10325 r0 top
R103 "0" 0603R 10950,10200 r90 top
R104 "22" 0603R 12300,10425 r180 top
R105 "50" 0603R 11825,10525 r0 top
R106 "2K2" 0603R 9800,10000 r270 top
R107 "82K" 0603R 10275,10000 r90 top
R108 "0" 0603R 10400,10000 r90 top
R109 "10K" 0402R#1 10525,10000 r270 top
R110 "22K" 0603R 10900,10000 r90 top
R111 "0" 0603R 11400,10000 r90 top
R112 "0" 0603R 11500,10000 r270 top
R113 "10K" 0402R#1 11575,10000 r90 top
R114 "10K" 0402R#1 11725,10000 r270 top
R115 "10K" 0402R#1 11875,10000 r270 top
R116 "10K" 0402R#1 12025,10000 r270 top
R117 "0" 0603R 11950,10000 r270 top
R118 "0" 0603R 12100,10000 r270 top
R119 "10K" 0402R#1 12175,10000 r270 top
R120 "330" 0603R 12350,10000 r270 top
R121 "22K" 0603R 11000,9875 r90 top
R122 "0" 0603R 11100,10000 r90 top
R123 "680" 0603R 11200,9875 r90 top
R124 "0" 0603R 11200,10000 r90 top
R125 "0" 0603R 11300,10000 r90 top
R126 "0" 0603R 11650,10000 r270 top
R127 "0" 0603R 11800,10000 r270 top
R128 "100" 0603R 9675,9800 r90 top
R129 "18K" 0603R 9925,9800 r90 top
R130 "680" 0603R 11100,9875 r90 top
R131 "680" 0603R 11300,9875 r90 top
R132 "100" 0603R 11500,9875 r90 top
R133 "100" 0603R 12250,10000 r90 top
R134 "220K" 0603R 12350,9875 r90 top
R135 "680" 0603R 10400,9800 r90 top
R136 "510" 0603R 11400,9875 r90 top
R137 "[N/A]" 0603R 10775,9250 r270 top
R138 "150" 0603R 10275,14250 r90 top
RS1 "22" RES8B_0402 12400,12225 r270 top
RV1 "[N/A]" 3314-J 10225,9525 r0 top
RV2 "3386P-201H[5%]" 3296W 9650,9150 r180 top
RV3 "10K" 3296W 10225,9150 r180 top
SB1 "" JP2_SMD 10775,13050 r180 top
SB2 "" JP2_SMD 11125,13050 r0 top
SB3 "" JP2_SMD 11225,13050 r0 top
SB4 "" JP2_SMD 10700,13050 r180 top
SB5 "" JP2_SMD 12025,13250 r90 top
SW1 "09.03290.01" SIP3 9625,12225 r0 top
SW2 "09.03290.01" SIP3 9625,12100 r0 top
T1 "9013" SOT-23 12575,10700 r180 top
T3 "STT5PF20V" SOT23-6L 11750,13400 r0 top
T4 "STT5PF20V" SOT23-6L 11950,13400 r0 top
TP1 "VREF" TP 11575,13600 r0 top
TP2 "AIN-" TP 12025,12975 r0 top
TP3 "AIN+" TP 12025,13100 r0 top
TP4 "Ground" TP 9425,12325 r0 top
TP5 "5V" TP 9425,12100 r0 top
TP6 "+3V3" TP 9275,10625 r0 top
TP7 "VDD_ADJ" TP 9275,10450 r0 top
TP8 "MIC+" TP 10425,9600 r0 top
TP9 "MIC_OUT" TP 10525,9600 r0 top
TR1 "FDN327N" SOT-23 10825,11800 r270 top
TR2 "FDN327N" SOT-23 11025,11800 r270 top
TR4 "FDN327N" SOT-23 11425,11000 r270 top
TS1 "TS_PAD" TS_PAD 10700,15225 r90 top
TS2 "TS_PAD" TS_PAD 11400,15225 r90 top
U1 "TS3702IPT" TSSOP8(6.4) 10275,14800 r90 top
U2 "SN74LVC2T45DCUT" VSSOP8 10200,14525 r90 top
U3 "SN74LVC2T45DCUT" VSSOP8 10575,14525 r90 top
U4 "SN74LVC2T45DCUT" VSSOP8 10325,14525 r90 top
U5 "SN74LVC2T45DCUT" VSSOP8 10450,14525 r90 top
U6 "74LV4060PW" TSSOP16 11800,14450 r0 top
U7 "USBLC6-2P6 (optional)" SOT-666 12650,14700 r270 top
U8 "ST3241EBPR" SSOP28 10250,14000 r90 top
U9 "SN74LVC1G04DCKT" PDSO-G5 11750,14200 r270 top
U10 "MAX9938FEUK+" SOT-23-5L 11925,14200 r270 top
U11 "STM32L152VBT6" TQ100_tool 11050,13725 r0 top locked
U12 "SN74LVC1G66DCKT" PDSO-G5 11750,13575 r270 top
U13 "SN74LVC2T45DCUT" VSSOP8 11299,12175 r90 top
U14 "SN74LVC2T45DCUT" VSSOP8 11174,12175 r90 top
U15 "SN74LVC2T45DCUT" VSSOP8 11424,12175 r90 top
U16 "SN74LVC2T45DCUT" VSSOP8 11049,12175 r90 top
U17 "TFDU6300" IR_VISHAY3 8975,12050 r90 top
U18 "STLM75M2E" SO8 10550,12000 r0 top
U19 "SN74LVC2T45DCUT" VSSOP8 11675,12175 r90 top
U20 "PD878-DP-FH-W-LV-6-RH" PD-878 10175,11550 r0 top locked
U21 "BNX002-01" BNX001 9025,11075 r180 top
U22 "LD1086D2M33" D2PAK/A 10525,11100 r0 top
U23 "STM32F103C8T6" LQFP48 11855,10795 r180 top
U24 "LD1086D2M" D2PAK/A 10525,10625 r0 top
U25 "KDMG15008-03" KS1508 11225,10550 r180 top
U26 "ZEN056V130A24LS" polyzen 9100,10500 r270 top
U27 "TS4990IST" MSOP8 10700,9975 r0 top
U28 "TS461CLT" SOT-23-5L 10100,9825 r0 top
U29 "KECG2740TBL" KEC2740 9325,9475 r270 top
U30 "MT008-A" JOY 11750,9200 r315 top
X1 "MC306-G-06Q-32.768 (manufacturer JFVNY)" SM8 10725,12900 r180 top
X2 "8MHz (with socket)" XTAL_SOCKET 11250,12900 r0 top
X3 "8MHz" SMT_XTAL 11975,11275 r0 top
Z1 "SMAJ5.0A-TR" 1R1C 8900,10500 r270 top

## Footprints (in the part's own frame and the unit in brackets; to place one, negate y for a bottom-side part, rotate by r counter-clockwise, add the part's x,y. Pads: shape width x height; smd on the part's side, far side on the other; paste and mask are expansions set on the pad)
1R1C [mm]
  rect 2.3x1.75 smd: 1(1.9,0) 2(-1.9,0)
  silkscreen extent -2.2,-1.5 2.2,1.5
2*3P#1 [mil]
  round 60 hole 40: 1(0,0) 2(100,0) 3(0,-100) 4(100,-100) 5(0,-200)
  silkscreen extent -50,-250 150,50
2*3P#2 [mil]
  round 60 hole 40: 1(0,0) 2(100,0) 3(0,-100) 4(100,-100) 5(0,-200) 6(100,-200)
  silkscreen extent -50,-250 150,50
2*4P [mil]
  round 60 hole 40: 1(0,0) 2(100,0) 3(0,-100) 4(100,-100) 5(0,-200) 6(100,-200) 7(0,-300) 8(100,-300)
  silkscreen extent -50,-350 150,50
2*25P [mil]
  round 60 hole 40: 1(0,0) 2(100,0) 3(0,-100) 4(100,-100) 5(0,-200) 6(100,-200) 7(0,-300) 8(100,-300) 9(0,-400) 10(100,-400) 11(0,-500) 12(100,-500) 13(0,-600) 14(100,-600) 15(0,-700) 16(100,-700) 17(0,-800) 18(100,-800) 19(0,-900) 20(100,-900) 21(0,-1000) 22(100,-1000) 23(0,-1100) 24(100,-1100) 25(0,-1200) 26(100,-1200) 27(0,-1300) 28(100,-1300) 29(0,-1400) 30(100,-1400) 31(0,-1500) 32(100,-1500) 33(0,-1600) 34(100,-1600) 35(0,-1700) 36(100,-1700) 37(0,-1800) 38(100,-1800) 39(0,-1900) 40(100,-1900) 41(0,-2000) 42(100,-2000) 43(0,-2100) 44(100,-2100) 45(0,-2200) 46(100,-2200) 47(0,-2300) 48(100,-2300) 49(0,-2400) 50(100,-2400)
  silkscreen extent -50,-2450 150,50
0402C [mil]
  rect 15x20 smd: 1(19.5,0) 2(-19.5,0)
  silkscreen extent -30,-14 32,14
0402R#1 [mil]
  rect 15x20 smd: 1(19.5,0) 2(-19.5,0)
  silkscreen extent -30,-14 32,14
0402R#2 [mil]
  rect 15x20 smd: 1(16.5,0) 2(-16.5,0)
  silkscreen extent -28,-14 28,14
0603C [mil]
  rect 30x30 smd: 1(27.5,0) 2(-27.5,0)
  silkscreen extent -50,-20 50,20
0603D [mil]
  rect 30x30 smd: 1(27.5,0) 2(-27.5,0)
  silkscreen extent -50,-25 55,25
0603L [mil]
  rect 30x30 smd: 1(27.5,0) 2(-27.5,0)
  silkscreen extent -50,-20 50,20
0603R [mil]
  rect 30x30 smd: 1(27.5,0) 2(-27.5,0)
  silkscreen extent -50,-20 50,20
0805C [mil]
  rect 40x50 smd: 1(40,0) 2(-40,0)
  silkscreen extent -70,-35 70,35
1206C [mil]
  rect 50x60 smd: 1(60,0) 2(-60,0)
  silkscreen extent -95,-40 95,40
3296W [mil]
  round 50 hole 28: 1(-100,0) 2(0,100) 3(100,0)
  silkscreen extent -190,-190 190,190
3314-J [mm]
  rect 2x1.3 smd: 1(2,1.15) 3(2,-1.15)
  rect 2x2 smd: 2(-2,0)
  silkscreen extent -2.54,-2.54 2.54,2.54
BNX001 [mm]
  round 1.8 hole 1.4: 1(2.5,2.5) 2(-2.5,2.5) 3(2.5,-2.5) 4(0,0) 5(5,0) 6(-2.5,-2.5)
  silkscreen extent -5,-5 5.76,5
C200M [mil]
  rect 100x80 smd paste-23.62 mask-23.62: 1(90,0) 2(-90,0)
  silkscreen extent -90,-105 95,105
C310M [mil]
  rect 200x120 smd paste-23.62 mask-23.62: 1(125,0) 2(-125,0)
  silkscreen extent -163,-163 163,163
D2PAK/A [mm]
  rect 2.8x1 smd: 1(-11.4,2.54) 2(-11.4,0)
  rect 8x10.2 smd: 2(0,0)
  rect 2.8x1.42 smd: 3(-11.4,-2.54)
  silkscreen extent -6.35,-5.08 4.06,5.08
DB9/M [mil]
  round 50 hole 50: 0(-538,55) 0(-523,55) 0(-508,55) 0(-493,55) 0(-478,55) 0(-463,55) 0(-448,55) 0(448,55) 0(463,55) 0(478,55) 0(493,55) 0(508,55) 0(523,55) 0(538,55)
  oval 170x80 hole 50: 0(-493,55) 0(493,55)
  rect 70x80 hole 38: 1(218,0)
  oval 70x80 hole 38: 2(109,0) 3(0,0) 4(-109,0) 5(-218,0) 6(164,110) 7(55,110) 8(-54,110) 9(-163,110)
  silkscreen extent -618,-100 618,410
DC10B [mil]
  round 45 hole 30: 1(244.09,-40) 1(244.09,-20) 1(244.09,20) 1(244.09,40) 2(82.05,-196.85) 2(102.05,-196.85) 2(142.05,-196.85) 2(162.05,-196.85) 3(0,-40) 3(0,-20) 3(0,20) 3(0,40)
  oval 80x180 hole 30: 1(244.09,0) 3(0,0)
  oval 180x80 hole 30: 2(122.05,-196.85)
  silkscreen extent -175,-170 290,180
FTSH-110-01-L-DV [mil]
  round 25 hole 38 unplated: 0(-200,0) 0(200,0)
  rect 25x100 smd: 1(-225,-85) 2(-225,85) 3(-175,-85) 4(-175,85) 5(-125,-85) 6(-125,85) 7(-75,-85) 8(-75,85) 9(-25,-85) 10(-25,85) 11(25,-85) 12(25,85) 13(75,-85) 14(75,85) 15(125,-85) 16(125,85) 17(175,-85) 18(175,85) 19(225,-85) 20(225,85)
  silkscreen extent -275,-102 275,102
IDC20S [mil]
  round 60 hole 40: 1(0,0) 2(100,0) 3(0,-100) 4(100,-100) 5(0,-200) 6(100,-200) 7(0,-300) 8(100,-300) 9(0,-400) 10(100,-400) 11(0,-500) 12(100,-500) 13(0,-600) 14(100,-600) 15(0,-700) 16(100,-700) 17(0,-800) 18(100,-800) 19(0,-900) 20(100,-900)
  silkscreen extent -125,-1100 250,200
IR_VISHAY3 [mm]
  rect 0.5x2 smd: 1(3.325,0) 2(2.375,0) 3(1.425,0) 4(0.475,0) 5(-0.475,0) 6(-1.425,0) 7(-2.375,0) 8(-3.325,0)
  silkscreen extent -4.18,-1.1 4.33,4.17
JOY [mil]
  round 27.56 hole 27.56 unplated: 0(-74.8,0)
  round 39.37 hole 39.37 unplated: 0(74.8,0)
  rect 40x70 smd: 1(-55.12,-122.05) 2(0,-122.05) 3(55.12,-122.05) 4(55.12,122.05) 5(0,122.05) 6(-55.12,122.05) G(-140,0) G(145,0)
  silkscreen extent -141,-150 146,150
JP2_SMD [mil]
  oct 15x30 smd rot 45: 1(-18,-8) 2(18,7)
  oct 15.75x30 smd rot 135: 1(-18,8)
  rect 26x26 smd rot 45: 2(13,0)
  oct 15x30 smd rot 135: 2(18,-7)
KEC2740 [mm]
  round 1.27 hole 0.762: 1(-1,-0.95) 2(-1,0.95)
  silkscreen extent -3,-3 3,3
KS1508 [mil]
  round 60 hole 40: 1(-149.61,0) 2(149.61,0)
  silkscreen extent -295,-295 295,295
LED2-28*32 [mm]
  rect 1.1x1.5 smd: 1(-0.75,-1.5) 2(-0.75,1.5) 3(0.75,1.5) 4(0.75,-1.5)
  silkscreen extent -1.27,-0.64 1.27,0.64
LQFP48 [mm]
  rect 0.2x1 smd: 1(-2.75,-4.25) 2(-2.25,-4.25) 3(-1.75,-4.25) 4(-1.25,-4.25) 5(-0.75,-4.25) 6(-0.25,-4.25) 7(0.25,-4.25) 8(0.75,-4.25) 9(1.25,-4.25) 10(1.75,-4.25) 11(2.25,-4.25) 12(2.75,-4.25) 25(2.75,4.25) 26(2.25,4.25) 27(1.75,4.25) 28(1.25,4.25) 29(0.75,4.25) 30(0.25,4.25) 31(-0.25,4.25) 32(-0.75,4.25) 33(-1.25,4.25) 34(-1.75,4.25) 35(-2.25,4.25) 36(-2.75,4.25)
  rect 1x0.2 smd: 13(4.25,-2.75) 14(4.25,-2.25) 15(4.25,-1.75) 16(4.25,-1.25) 17(4.25,-0.75) 18(4.25,-0.25) 19(4.25,0.25) 20(4.25,0.75) 21(4.25,1.25) 22(4.25,1.75) 23(4.25,2.25) 24(4.25,2.75) 37(-4.25,2.75) 38(-4.25,2.25) 39(-4.25,1.75) 40(-4.25,1.25) 41(-4.25,0.75) 42(-4.25,0.25) 43(-4.25,-0.25) 44(-4.25,-0.75) 45(-4.25,-1.25) 46(-4.25,-1.75) 47(-4.25,-2.25) 48(-4.25,-2.75)
  silkscreen extent -3.81,-3.81 3.81,3.81
markpoint_1.0 [mil]
  round 40 smd: 0(0,0)
MB542 [mil]
  round 125.98 hole 125.98 unplated: 0(-3129.92,0) 0(-3129.92,1417.72) 0(0,0)
  round 60 hole 40: 1(-80.98,1462.72) 2(19.02,1462.72) 3(-80.98,1362.72) 4(19.02,1362.72) 5(-80.98,1262.72) 6(19.02,1262.72) 7(-80.98,1162.72) 8(19.02,1162.72) 9(-80.98,462.72) 10(19.02,462.72) 11(-80.98,362.72) 12(19.02,362.72) 13(-80.98,262.72) 14(19.02,262.72) 15(-80.98,162.72) 16(19.02,162.72)
  silkscreen extent -3219,-157 89,1575
MSD(PJS008) [mm]
  round 0.7 hole 0.7 unplated: 0(0,0) 0(0,7.55)
  rect 1.6x0.8 smd: 1(-5.8,1.475) 2(-5.8,2.575) 3(-5.8,3.675) 4(-5.8,4.775) 5(-5.8,5.875) 6(-5.8,6.975) 7(-5.8,8.075) 8(-5.8,9.175)
  rect 1.6x0.85 smd: 9(-5.8,10.325)
  rect 1.4x1.95 smd: 10(4.4,11.225)
  rect 3.5x1.6 smd: G1(-3.65,-3.4)
  rect 3.1x1.5 smd: G2(7.35,11.45)
  rect 3.5x1.4 smd: G3(7.35,-3.5)
  rect 3.1x1.2 smd: G4(-4.15,11.6)
  silkscreen extent -5.07,-3.81 9.28,11.43
MSOP8 [mm]
  rect 0.3x0.9 smd: 1(-0.975,-2.151) 2(-0.325,-2.151) 3(0.325,-2.151) 4(0.975,-2.151) 5(0.975,2.151) 6(0.325,2.151) 7(-0.325,2.151) 8(-0.975,2.151)
  silkscreen extent -1.32,-1.36 1.32,1.36
PB10 [mil]
  rect 60x40 smd: 1(-177.17,-87.5) 2(-177.17,87.5) 3(177.17,87.5) 4(177.17,-87.5)
  silkscreen extent -125,-125 125,125
PD-878 [mil]
  rect 60x100 hole 40: 1(1,1)
  oval 60x100 hole 40: 2(101,1) 3(201,1) 4(301,1) 5(401,1) 6(501,1) 7(601,1) 8(701,1) 9(801,1) 10(901,1) 11(1001,1) 12(1101,1) 13(1201,1) 14(1301,1) 15(1401,1) 16(1501,1) 17(1601,1) 18(1701,1) 19(1701,980) 20(1601,980) 21(1501,980) 22(1401,980) 23(1301,980) 24(1201,980) 25(1101,980) 26(1001,980) 27(901,980) 28(801,980) 29(701,980) 30(601,980) 31(501,980) 32(401,980) 33(301,980) 34(201,980) 35(101,980) 36(1,980)
  silkscreen extent -49,82 1751,899
PDSO-G5 [mil]
  rect 30x16 smd: 1(-43.31,25.59) 2(-43.31,0) 3(-43.31,-25.59) 4(43.31,-23.62) 5(43.31,25.59)
  silkscreen extent -33,-43 32,42
PJST-613 [mm]
  round 2 hole 1.2: 1(4.2,0) 10(12,0)
  round 2 hole 1.4: 2(11,-4)
  round 1.3 hole 1.3 unplated: G1(7.5,2) G2(7.5,-4)
  silkscreen extent -3.2,-5 12.6,3.5
polyzen [mm]
  rect 0.8x2.21 smd: 1(1.714,0)
  rect 0.7x0.94 smd: 2(-1.714,-0.635) 3(-1.714,0.635)
  silkscreen extent -1.97,-2.03 2.1,2.03
PVT901 [mil]
  round 60 hole 30: 1(0,50) 2(0,-50)
  silkscreen extent -92,-98 92,98
RES8B_0402 [mm]
  rect 0.25x0.5 smd: 1(-1.75,-0.508) 2(-1.75,0.508) 3(-1.25,-0.508) 4(-1.25,0.508) 5(-0.75,-0.508) 6(-0.75,0.508) 7(-0.25,-0.508) 8(-0.25,0.508) 9(0.25,-0.508) 10(0.25,0.508) 11(0.75,-0.508) 12(0.75,0.508) 13(1.25,-0.508) 14(1.25,0.508) 15(1.75,-0.508) 16(1.75,0.508)
  silkscreen extent -2.1,-0.5 2.1,0.5
SIP2 [mil]
  round 60 hole 40: 1(0,0) 2(100,0)
  silkscreen extent -50,-50 150,50
SIP3 [mil]
  rect 60x60 hole 40: 1(0,0)
  round 60 hole 40: 2(100,0) 3(200,0)
  silkscreen extent -50,-50 250,50
SM8 [mm]
  rect 1.9x1.3 smd: 1(-2.75,1.6) 2(2.75,1.6) 3(2.75,-1.6) 4(-2.75,-1.6)
  silkscreen extent -4.44,-1.91 4.44,1.91
SMT_XTAL [mil]
  rect 150x50 smd: 1(-195,0) 2(195,0)
  silkscreen extent -214,-89 214,89
SO8 [mil]
  rect 20x60 smd: 1(-75,-112.5) 2(-25,-112.5) 3(25,-112.5) 4(75,-112.5) 5(75,112.5) 6(25,112.5) 7(-25,112.5) 8(-75,112.5)
  silkscreen extent -105,-52 105,48
SOD-323 [mm]
  rect 0.6x0.45 smd: 1(1.143,0) 2(-1.143,0)
  silkscreen extent -0.67,-0.57 0.67,0.57
SOT23-6L [mm]
  rect 0.3x0.9 smd: 1(-0.95,-1.05) 2(0,-1.05) 3(0.95,-1.05) 4(0.95,1.05) 5(0,1.05) 6(-0.95,1.05)
  silkscreen extent -1.45,-0.55 1.25,0.55
SOT-23 [mil]
  rect 36x36 smd: 1(40,37.5) 2(40,-37.5)
  rect 50x36 smd: 3(-40,0.5)
  silkscreen extent -45,-58 45,58
SOT-23-5L [mil]
  rect 30x16 smd: 1(-53.15,37.4) 2(-53.15,0) 3(-53.15,-37.4) 4(53.15,-37.4) 5(53.15,37.4)
  silkscreen extent -33,-58 32,57
SOT-666 [mm]
  rect 0.279x1.16 smd: 1(-0.5,-0.795) 2(0,-0.795) 3(0.5,-0.795) 4(0.5,0.795) 5(0,0.795) 6(-0.5,0.795)
  silkscreen extent -0.88,-0.82 0.88,0.82
SSOP28 [mm]
  rect 0.95x0.3 smd: 1(-3.8,4.225) 2(-3.8,3.575) 3(-3.8,2.925) 4(-3.8,2.275) 5(-3.8,1.625) 6(-3.8,0.975) 7(-3.8,0.325) 8(-3.8,-0.325) 9(-3.8,-0.975) 10(-3.8,-1.625) 11(-3.8,-2.275) 12(-3.8,-2.925) 13(-3.8,-3.575) 14(-3.8,-4.225) 15(3.8,-4.225) 16(3.8,-3.575) 17(3.8,-2.925) 18(3.8,-2.275) 19(3.8,-1.625) 20(3.8,-0.975) 21(3.8,-0.325) 22(3.8,0.325) 23(3.8,0.975) 24(3.8,1.625) 25(3.8,2.275) 26(3.8,2.925) 27(3.8,3.575) 28(3.8,4.225)
  silkscreen extent -2.56,-4.55 2.56,4.55
TAN-A [mil]
  rect 50x60 smd: 1(55,0) 2(-55,0)
  silkscreen extent -95,-45 105,45
TP [mil]
  round 60 hole 40: 1(0,0)
  silkscreen extent -45,-45 45,45
TQ100_tool [mm]
  rect 2.5x1.5 smd rot 135: 0(-8.06,-8.06) 0(8.06,8.06)
  rect 2.5x1.5 smd rot 45: 0(-8.06,8.06) 0(8.06,-8.06)
  round 1.5 hole 1.5 unplated: 0(-5,0) 0(5,0)
  rect 0.2x1.5 smd: 1(-6,-7.725) 2(-5.5,-7.725) 3(-5,-7.725) 4(-4.5,-7.725) 5(-4,-7.725) 6(-3.5,-7.725) 7(-3,-7.725) 8(-2.5,-7.725) 9(-2,-7.725) 10(-1.5,-7.725) 11(-1,-7.725) 12(-0.5,-7.725) 13(0,-7.725) 14(0.5,-7.725) 15(1,-7.725) 16(1.5,-7.725) 17(2,-7.725) 18(2.5,-7.725) 19(3,-7.725) 20(3.5,-7.725) 21(4,-7.725) 22(4.5,-7.725) 23(5,-7.725) 24(5.5,-7.725) 25(6,-7.725) 51(6,7.725) 52(5.5,7.725) 53(5,7.725) 54(4.5,7.725) 55(4,7.725) 56(3.5,7.725) 57(3,7.725) 58(2.5,7.725) 59(2,7.725) 60(1.5,7.725) 61(1,7.725) 62(0.5,7.725) 63(0,7.725) 64(-0.5,7.725) 65(-1,7.725) 66(-1.5,7.725) 67(-2,7.725) 68(-2.5,7.725) 69(-3,7.725) 70(-3.5,7.725) 71(-4,7.725) 72(-4.5,7.725) 73(-5,7.725) 74(-5.5,7.725) 75(-6,7.725)
  rect 1.5x0.2 smd: 26(7.725,-6) 27(7.725,-5.5) 28(7.725,-5) 29(7.725,-4.5) 30(7.725,-4) 31(7.725,-3.5) 32(7.725,-3) 33(7.725,-2.5) 34(7.725,-2) 35(7.725,-1.5) 36(7.725,-1) 37(7.725,-0.5) 38(7.725,0) 39(7.725,0.5) 40(7.725,1) 41(7.725,1.5) 42(7.725,2) 43(7.725,2.5) 44(7.725,3) 45(7.725,3.5) 46(7.725,4) 47(7.725,4.5) 48(7.725,5) 49(7.725,5.5) 50(7.725,6) 76(-7.725,6) 77(-7.725,5.5) 78(-7.725,5) 79(-7.725,4.5) 80(-7.725,4) 81(-7.725,3.5) 82(-7.725,3) 83(-7.725,2.5) 84(-7.725,2) 85(-7.725,1.5) 86(-7.725,1) 87(-7.725,0.5) 88(-7.725,0) 89(-7.725,-0.5) 90(-7.725,-1) 91(-7.725,-1.5) 92(-7.725,-2) 93(-7.725,-2.5) 94(-7.725,-3) 95(-7.725,-3.5) 96(-7.725,-4) 97(-7.725,-4.5) 98(-7.725,-5) 99(-7.725,-5.5) 100(-7.725,-6)
  silkscreen extent -5.59,-5.71 -5.08,-5.21
TS_PAD [mm]
  round 10 smd: 1(0,0)
TSSOP8(6.4) [mm]
  rect 0.25x1 smd: 1(-0.975,-3.2) 2(-0.325,-3.2) 3(0.325,-3.2) 4(0.975,-3.2) 5(0.975,3.2) 6(0.325,3.2) 7(-0.325,3.2) 8(-0.975,3.2)
  silkscreen extent -1.3,-1.94 1.3,1.94
TSSOP16 [mm]
  rect 0.3x1.15 smd: 1(-2.275,-3.2) 2(-1.625,-3.2) 3(-0.975,-3.2) 4(-0.325,-3.2) 5(0.325,-3.2) 6(0.975,-3.2) 7(1.625,-3.2) 8(2.275,-3.2) 9(2.275,3.2) 10(1.625,3.2) 11(0.975,3.2) 12(0.325,3.2) 13(-0.325,3.2) 14(-0.975,3.2) 15(-1.625,3.2) 16(-2.275,3.2)
  silkscreen extent -2.6,-2.26 2.6,2.22
USB-B [mil]
  round 120 hole 95: 0(-291,-185) 0(189,-185)
  round 50 hole 30: 1(0,0) 2(-98,0) 3(-98,-80) 4(0,-80)
  silkscreen extent -365,-488 263,57
VB334 [mm]
  round 2 hole 1.3: 1(-3.125,3.125) 2(3.125,3.125) 3(3.125,-3.125) 4(-3.125,-3.125)
  round 2.032 hole 1.27: 5(0,0)
  silkscreen extent -5.5,-5.5 5.5,5.5
VSSOP8 [mm]
  rect 0.5x0.25 smd: 1(-1.5,0.75) 2(-1.5,0.25) 3(-1.5,-0.25) 4(-1.5,-0.75) 5(1.5,-0.75) 6(1.5,-0.25) 7(1.5,0.25) 8(1.5,0.75)
  silkscreen extent -1.09,-1 1.09,1
XTAL_SOCKET [mil]
  round 80 hole 53: 1(100,0) 2(-100,0)
  silkscreen extent -215,-89 214,89

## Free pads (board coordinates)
  round 137.8 hole 137.8 unplated: 0(9000,9000) 0(9000,15350) 0(13050,9000) 0(13050,15350)
  round 137.79 hole 137.79 unplated: 0(10250,15225) 0(11850,15225)

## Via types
v1: diameter 15, hole 8, TopLayer to BottomLayer, tented both sides, 315 vias
v2: diameter 15, hole 8, TopLayer to BottomLayer, 230 vias
v3: diameter 25, hole 15, TopLayer to BottomLayer, tented both sides, 31 vias
v4: diameter 25, hole 16, TopLayer to BottomLayer, 6 vias
v5: diameter 25, hole 16, TopLayer to BottomLayer, tented both sides, 2 vias

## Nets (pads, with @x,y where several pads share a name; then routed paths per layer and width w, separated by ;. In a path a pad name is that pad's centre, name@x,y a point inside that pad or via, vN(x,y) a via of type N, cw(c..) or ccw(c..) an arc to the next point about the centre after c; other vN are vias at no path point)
+3V3: C1.2 C2.2 C3.2 C4.2 C14.2 C35.2 C36.2 C37.2 C38.2 C40.1 C41.2 C44.1 C50.2 C51.1 C55.1 C57.1 C59.2 C62.2 C64.2 C66.1 CN4.4 CN6.48 CN10.4 CN14.9 CN14.10 JP13.3 LD1.1 LD2.1 LD3.1 LD4.1 LD8.1 R5.2 R9.2 R55.1 R60.1 R63.2 R66.2 R87.2 R91.2 R102.2 R109.2 T1.3 TP6.1 U1.8 U2.8 U3.8 U4.8 U5.8 U8.22 U8.26 U13.8 U14.8 U15.8 U16.8 U17.7 U18.8 U19.1 U22.2 U23.1 U23.9 U23.24 U23.36 U23.48 U27.6 U28.5 | length 17983.5
  TopLayer w5: U17.7@8975,11956.5 9041.5,11956.5 9085,12000 C44.1@9105.5,12000 v1(9105.5,12024.5) ; LD8.1@9977.5,15225 v1(10015,15225) ; v1(10000,14775) R5.2@10030.5,14775 ; C14.2@10024.5,14230 C14.2@10025,14230.5 ; U28.5@10153.15,9862.4 v1(10187.4,9862.4) ; R63.2@10375,12019.5 C41.2@10375,12080.5 v1(10420.5,12080.5) 10452.5,12112.5 U18.8@10475,12112.5 ; R9.2@10544.5,14775 v1(10575,14775) ; U3.8@10545,14584.53 U3.8@10545.47,14584.06 ; v1(11000,9445) LD4.1@11000,9497.5 ; C38.2@11029.5,12324 C38.2@11030.5,12325 ; v1(11125,9445) LD3.1@11125,9497.5 ; U14.8@11144.47,12234.06 U14.8@11145,12234.58 ; v1(11250,9445) LD2.1@11250,9497.5 ; U13.8@11269.47,12234.06 U13.8@11270,12234.58 ; v1(11375,9445) LD1.1@11375,9497.5 ; U23.9@11805.5,10962.61 U23.9@11805.79,10962.32 ; v3@12727.01,12912.99 v3(12730,12910)
  TopLayer w12: R60.1@9152.5,12100 9260,12100 9275,12115 C40.1@9275,12145 ; R55.1@9152.5,12200 v1(9152.5,12242.5) ; v2(9975,14250) 9994.5,14230.5 C14.2@10025,14230.5 ; 10042,11417 10044.5,11414.5 C51.1@10044.5,11350 ; v2(10125,14200) 10134.84,14190.16 U8.26@10134.84,14149.61 ; U1.8@10149.02,14761.61 10211.61,14761.61 v2(10225,14775) ; U2.8@10170.47,14584.06 10170.47,14620.47 10180.5,14630.5 C4.2@10180.5,14675 ; U8.22@10237.2,14149.61 10237.2,14197.2 v2(10240,14200) ; U4.8@10295.47,14584.06 v1(10295.47,14625.47) 10305.5,14635.5 C1.2@10305.5,14675 ; U5.8@10420,14584.53 v1(10420,14625) 10430.5,14635.5 C2.2@10430.5,14675 ; R109.2@10525.5,10020 10550.5,10020 10555.5,10025 v2(10625,10025) ; U3.8@10545,14584.53 v1(10545,14625) 10555.5,14635.5 C3.2@10555.5,14675 ; C66.1@10650,10172.5 10650,10125 10625,10100 10625,10000 10640,9985 10687.8,9985 10712.8,10010 U27.6@10712.8,10059.69 ; U16.8@11019.47,12234.06 11019.47,12274.47 11030.5,12285.5 C38.2@11030.5,12325 ; U14.8@11144.47,12234.06 11144.47,12274.47 11155.5,12285.5 C35.2@11155.5,12325 ; U13.8@11269.47,12234.06 v1@11269.47,12274.47 ; v1(11270,12275) 11270,12289.5 11280.5,12300 C36.2@11280.5,12325 ; U15.8@11394.47,12234.06 v1(11394.47,12274.47) 11405.5,12285.5 C37.2@11405.5,12325 ; v1(11525,10949) R91.2@11525,10980.5 ; C62.2@11575,10655.5 11615.5,10655.5 11646.73,10686.73 U23.24@11687.68,10686.73 ; v2@11645.47,12079.53 U19.1@11645.47,12115.94 ; v2(11650,12075) 11655.5,12069.5 C50.2@11655.5,12025 ; v1(11697.5,11092.5) R87.2@11697.5,11125 ; v1(11805,10998) C57.1@11805,11049.5 ; U23.9@11805.79,10962.32 v1@11805.79,10997.21 ; U23.36@11963.27,10627.68 11963.27,10600.73 12019.5,10544.5 C64.2@12019.5,10525 ; U23.1@11963.27,10962.32 v1@11963.27,11000.73 ; U23.48@12022.32,10903.27 12069.27,10903.27 12085.5,10919.5 12150,10919.5 12219.5,10850 12375,10850 12425,10800 12425,10750 12475.5,10699.5 T1.3@12615,10699.5 ; CN10.4@12250,10800 12250,10850 ; CN14.9@12519.02,10312.72 CN14.10@12619.02,10312.72 ; CN4.4@12674.65,12910 v3(12730,12910)
  TopLayer w20: v2(11750,10325) R102.2@11797.5,10325
  TopLayer w30: C55.1@9875,11045 9925,11045 v3(9980,11100) v3@10295,11100
  MidLayer1 w20: v1(9152.5,12242.5) 9175,12265 9175,12400 9275,12500 9675,12500 CN6.48@9725,12550 ; TP6.1@9275,10625 9275,10615 9380,10720 9380,11100 ; 9977,14775 v1(10000,14775) ; 10175,14575 v2(10175,14625) 10225,14675 v2(10225,14775) ; v3@10295,11100 9380,11100 ; 10295.47,14579.53 v1(10295.47,14625.47) ; v3(10420,11920) v1@10420,12080 ; 10420,14575 v1(10420,14625) ; v1(10420.5,12080.5) 10590,12250 11580,12250 11650,12180 v2(11650,12075) ; v1(10575,14775) 10575,14655 10495,14575 10000,14575 9972,14603 9972,14900 10015,14943 v1(10015,15225) 9915,15325 9275,15325 8850,14900 8850,12580 9200,12230 v1(9200,12100) 9124.5,12024.5 v1(9105.5,12024.5) 8925,11844 8925,11450 9075,11300 9180,11300 9380,11100 ; 11270,12250 v1(11270,12275) ; 11394.47,12250.53 v1(11394.47,12274.47) ; 12250,11200 12600,11550 12600,12780 v3(12730,12910) ; 12412.28,10312.72 CN14.10@12619.02,10312.72 12750,10181.73
  other v1: 11965,10600 11641,10681 11963,11001 11145,12275 11030,12300
  other v2: 12075,10910
  other v3: 10180,11100 10240,11100 10300,11103 10350,11900 10350,11950
+5V: C65.1 CN14.13 CN14.14 JP12.2 JP12.4 JP12.6 JP12.8 R72.2 TP5.1 U22.3 U24.3 | length 4272.1
  TopLayer w5: JP12.2@8997.5,11652.5 R72.2@8997.5,11750
  TopLayer w12: JP12.8@9300,11650 9370,11650 9425,11705 TP5.1@9425,12100
  TopLayer w30: JP12.2@9000,11650 JP12.8@9300,11650 ; C65.1@9640,10475 9715,10475 9770,10420 10036.18,10420 v3(10076.18,10460) U24.3@10076.18,10525 ; v3(9965,10525) v3(10165,10525) ; v3(9980,11000) v3(10165,11000) ; v3(10076.18,10946.18) U22.3@10076.18,11000
  MidLayer1 w30: 10505,10363 10912,10363 11325,9950 12356.3,9950 CN14.13@12519.02,10112.72 CN14.14@12619.02,10112.72
AIN_1: R85.1 R90.2 U23.10 | length 1263.6
  TopLayer w5: U23.10@11786.1,10962.32 11786.1,10926.1 11797.21,10915 11970,10915 12030,10975 12555,10975 12575,10995 12575,11045 12590,11060 12819.5,11060 ; R90.2@12819.5,11025 R85.1@12819.5,11125
D5V: CN6.49 CN7.19 JP12.3 | length 5122.6
  TopLayer w30: JP12.3@9100,11550 9100,11515 9150,11465 9415,11465 9535,11585 9535,12360 CN6.49@9625,12450
  MidLayer1 w50: v3@10025,12600 10050,12625 11550,12625 11675,12750 11675,12925 12225,13475 12225,13875 CN7.19@12300,13950
  BottomLayer w20: CN6.49@9625,12450 9672.5,12402.5 9879.5,12402.5 9912,12435
  BottomLayer w25: CN6.49@9625,12450 9675,12500 9793,12500
  other v3: 10025.23,12600.23 10075,12625
E5V: C58.1 JP12.1 U21.3 | length 1187.9
  TopLayer w20: 9005,11395 9060,11340
  TopLayer w50: U21.3@8925,11160 8925,11265 9000,11340 ; JP12.1@9000,11525 9000,11340 ; C58.1@9375,10873 9375,11123 ; 9375,11125 9160,11340 9000,11340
